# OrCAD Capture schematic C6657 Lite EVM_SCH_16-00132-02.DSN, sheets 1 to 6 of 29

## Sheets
1 PAGE06 : POWER SEQUENCE: title: POWER SEQUENCE; rev: 2.9; company: eInfochips; note: TMDSEVM6657
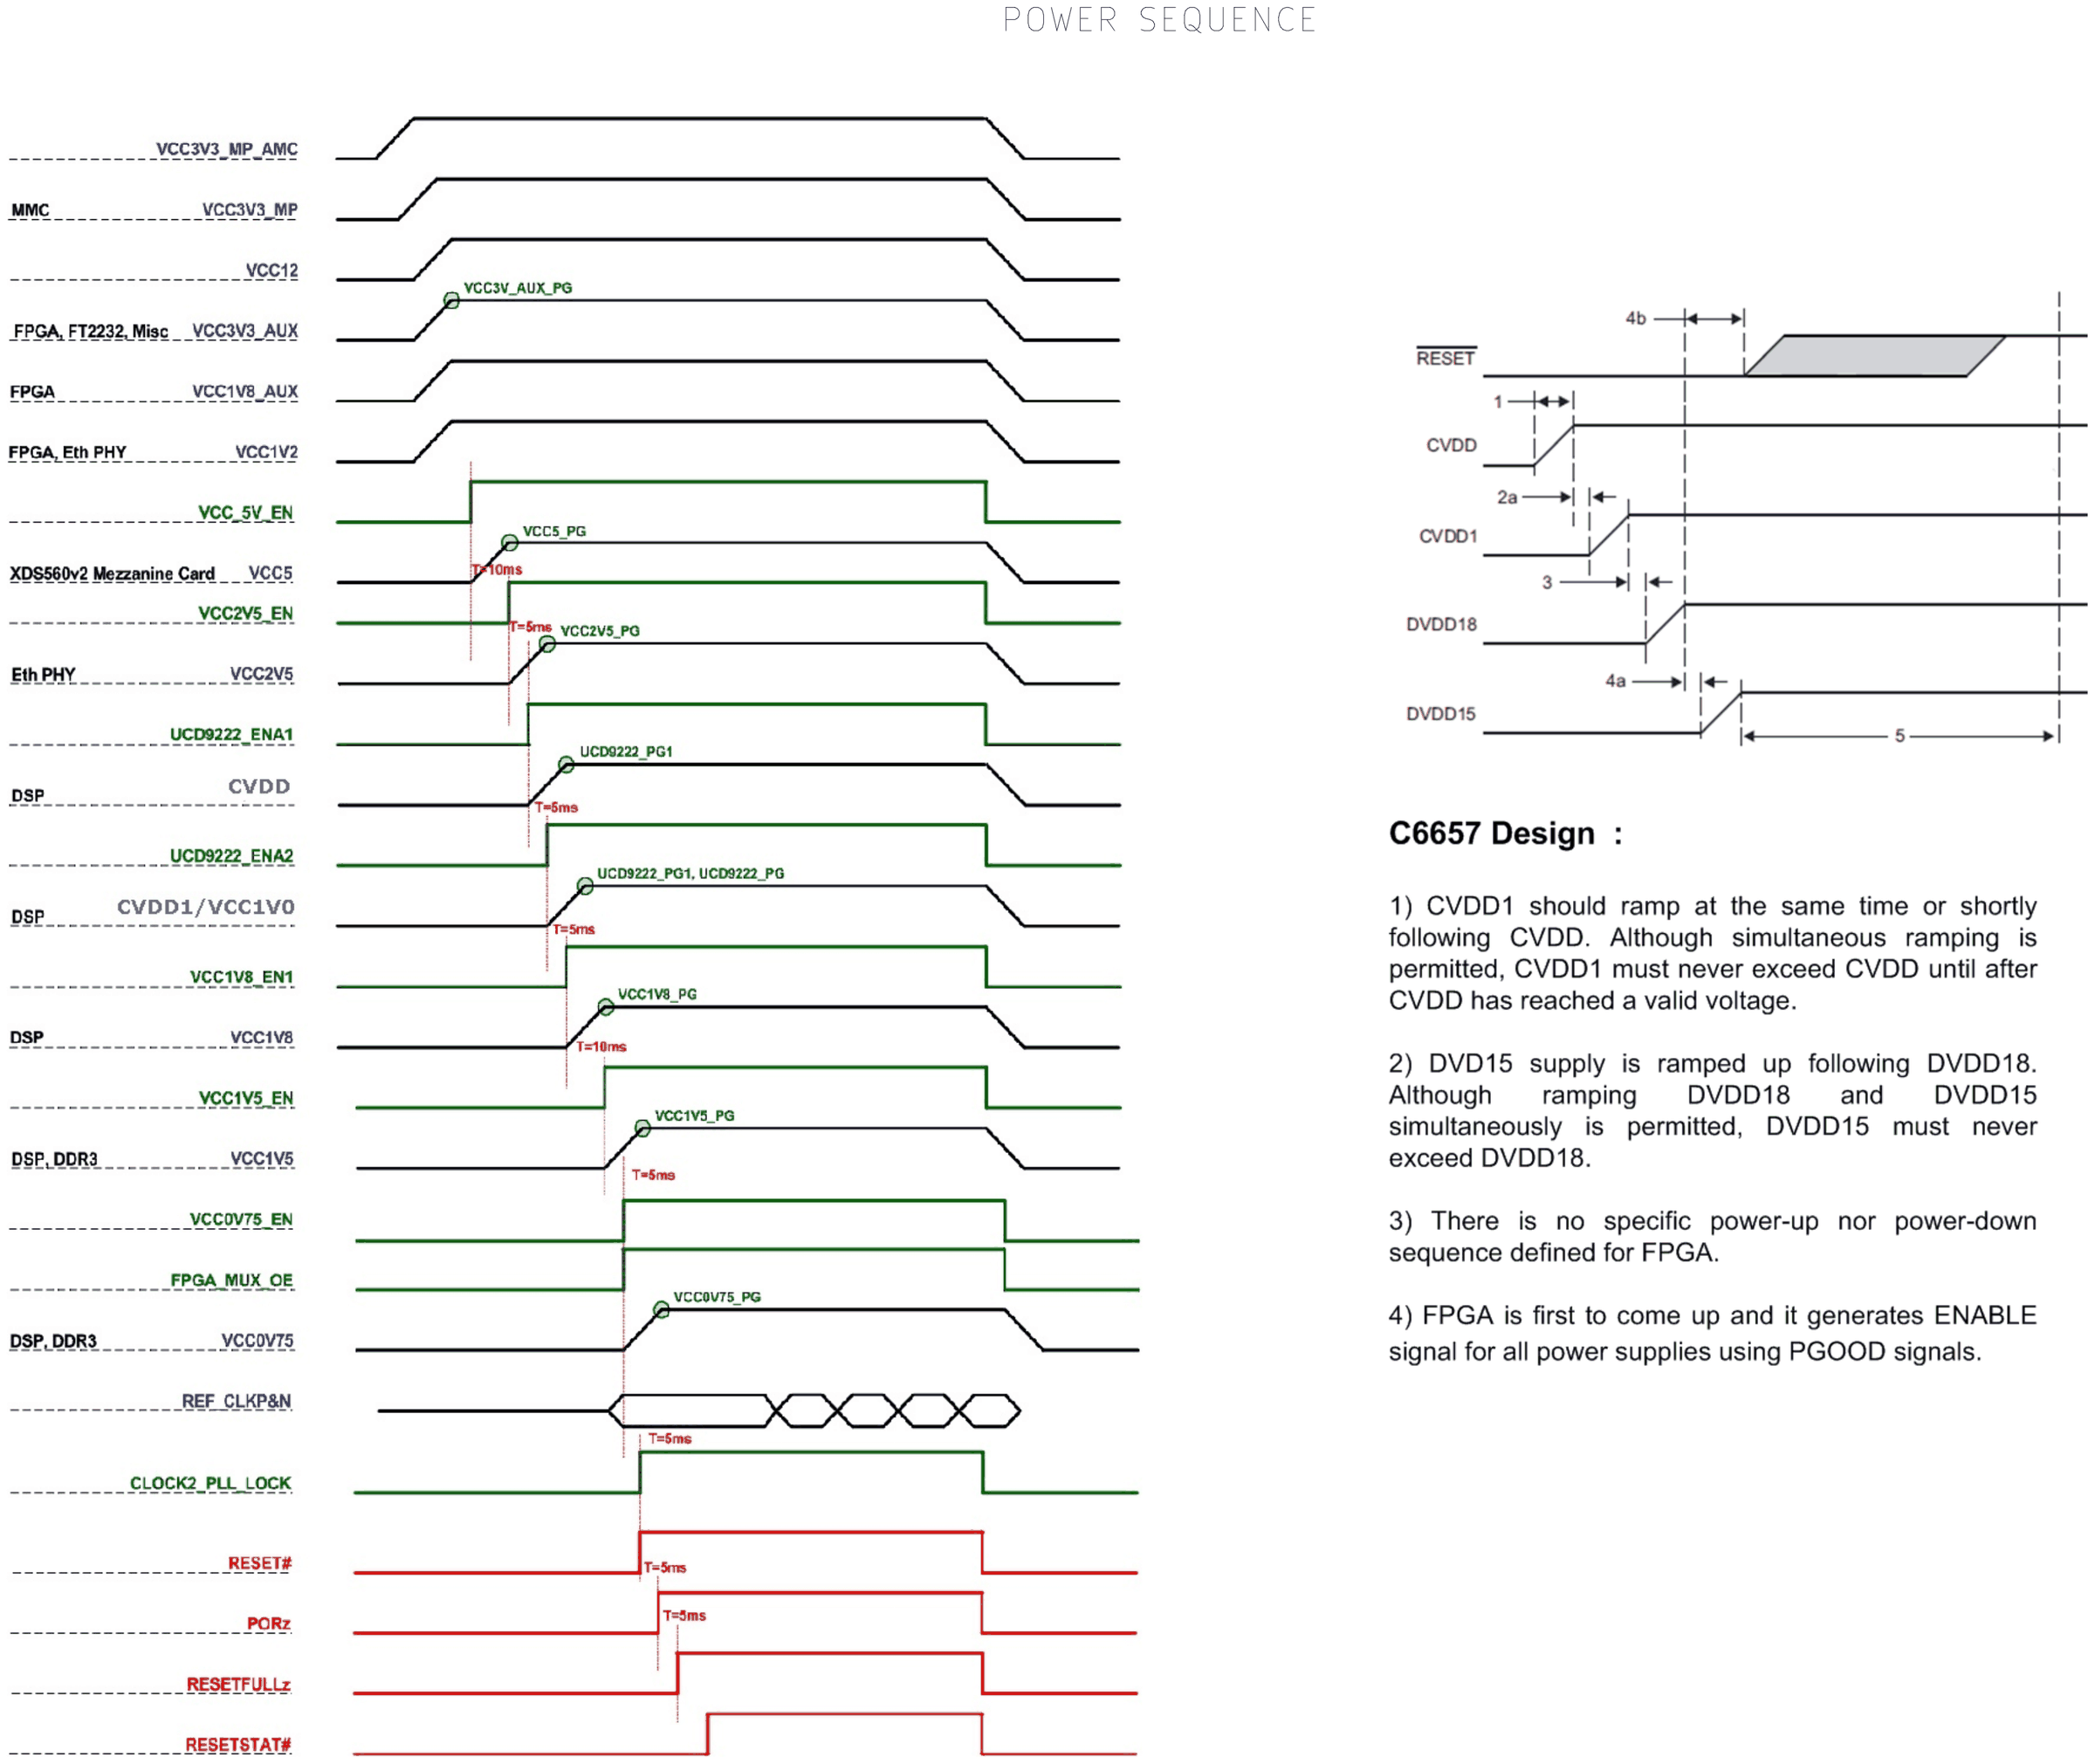
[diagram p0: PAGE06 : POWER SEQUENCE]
2 PAGE01 : COVER PAGE: title: COVER PAGE
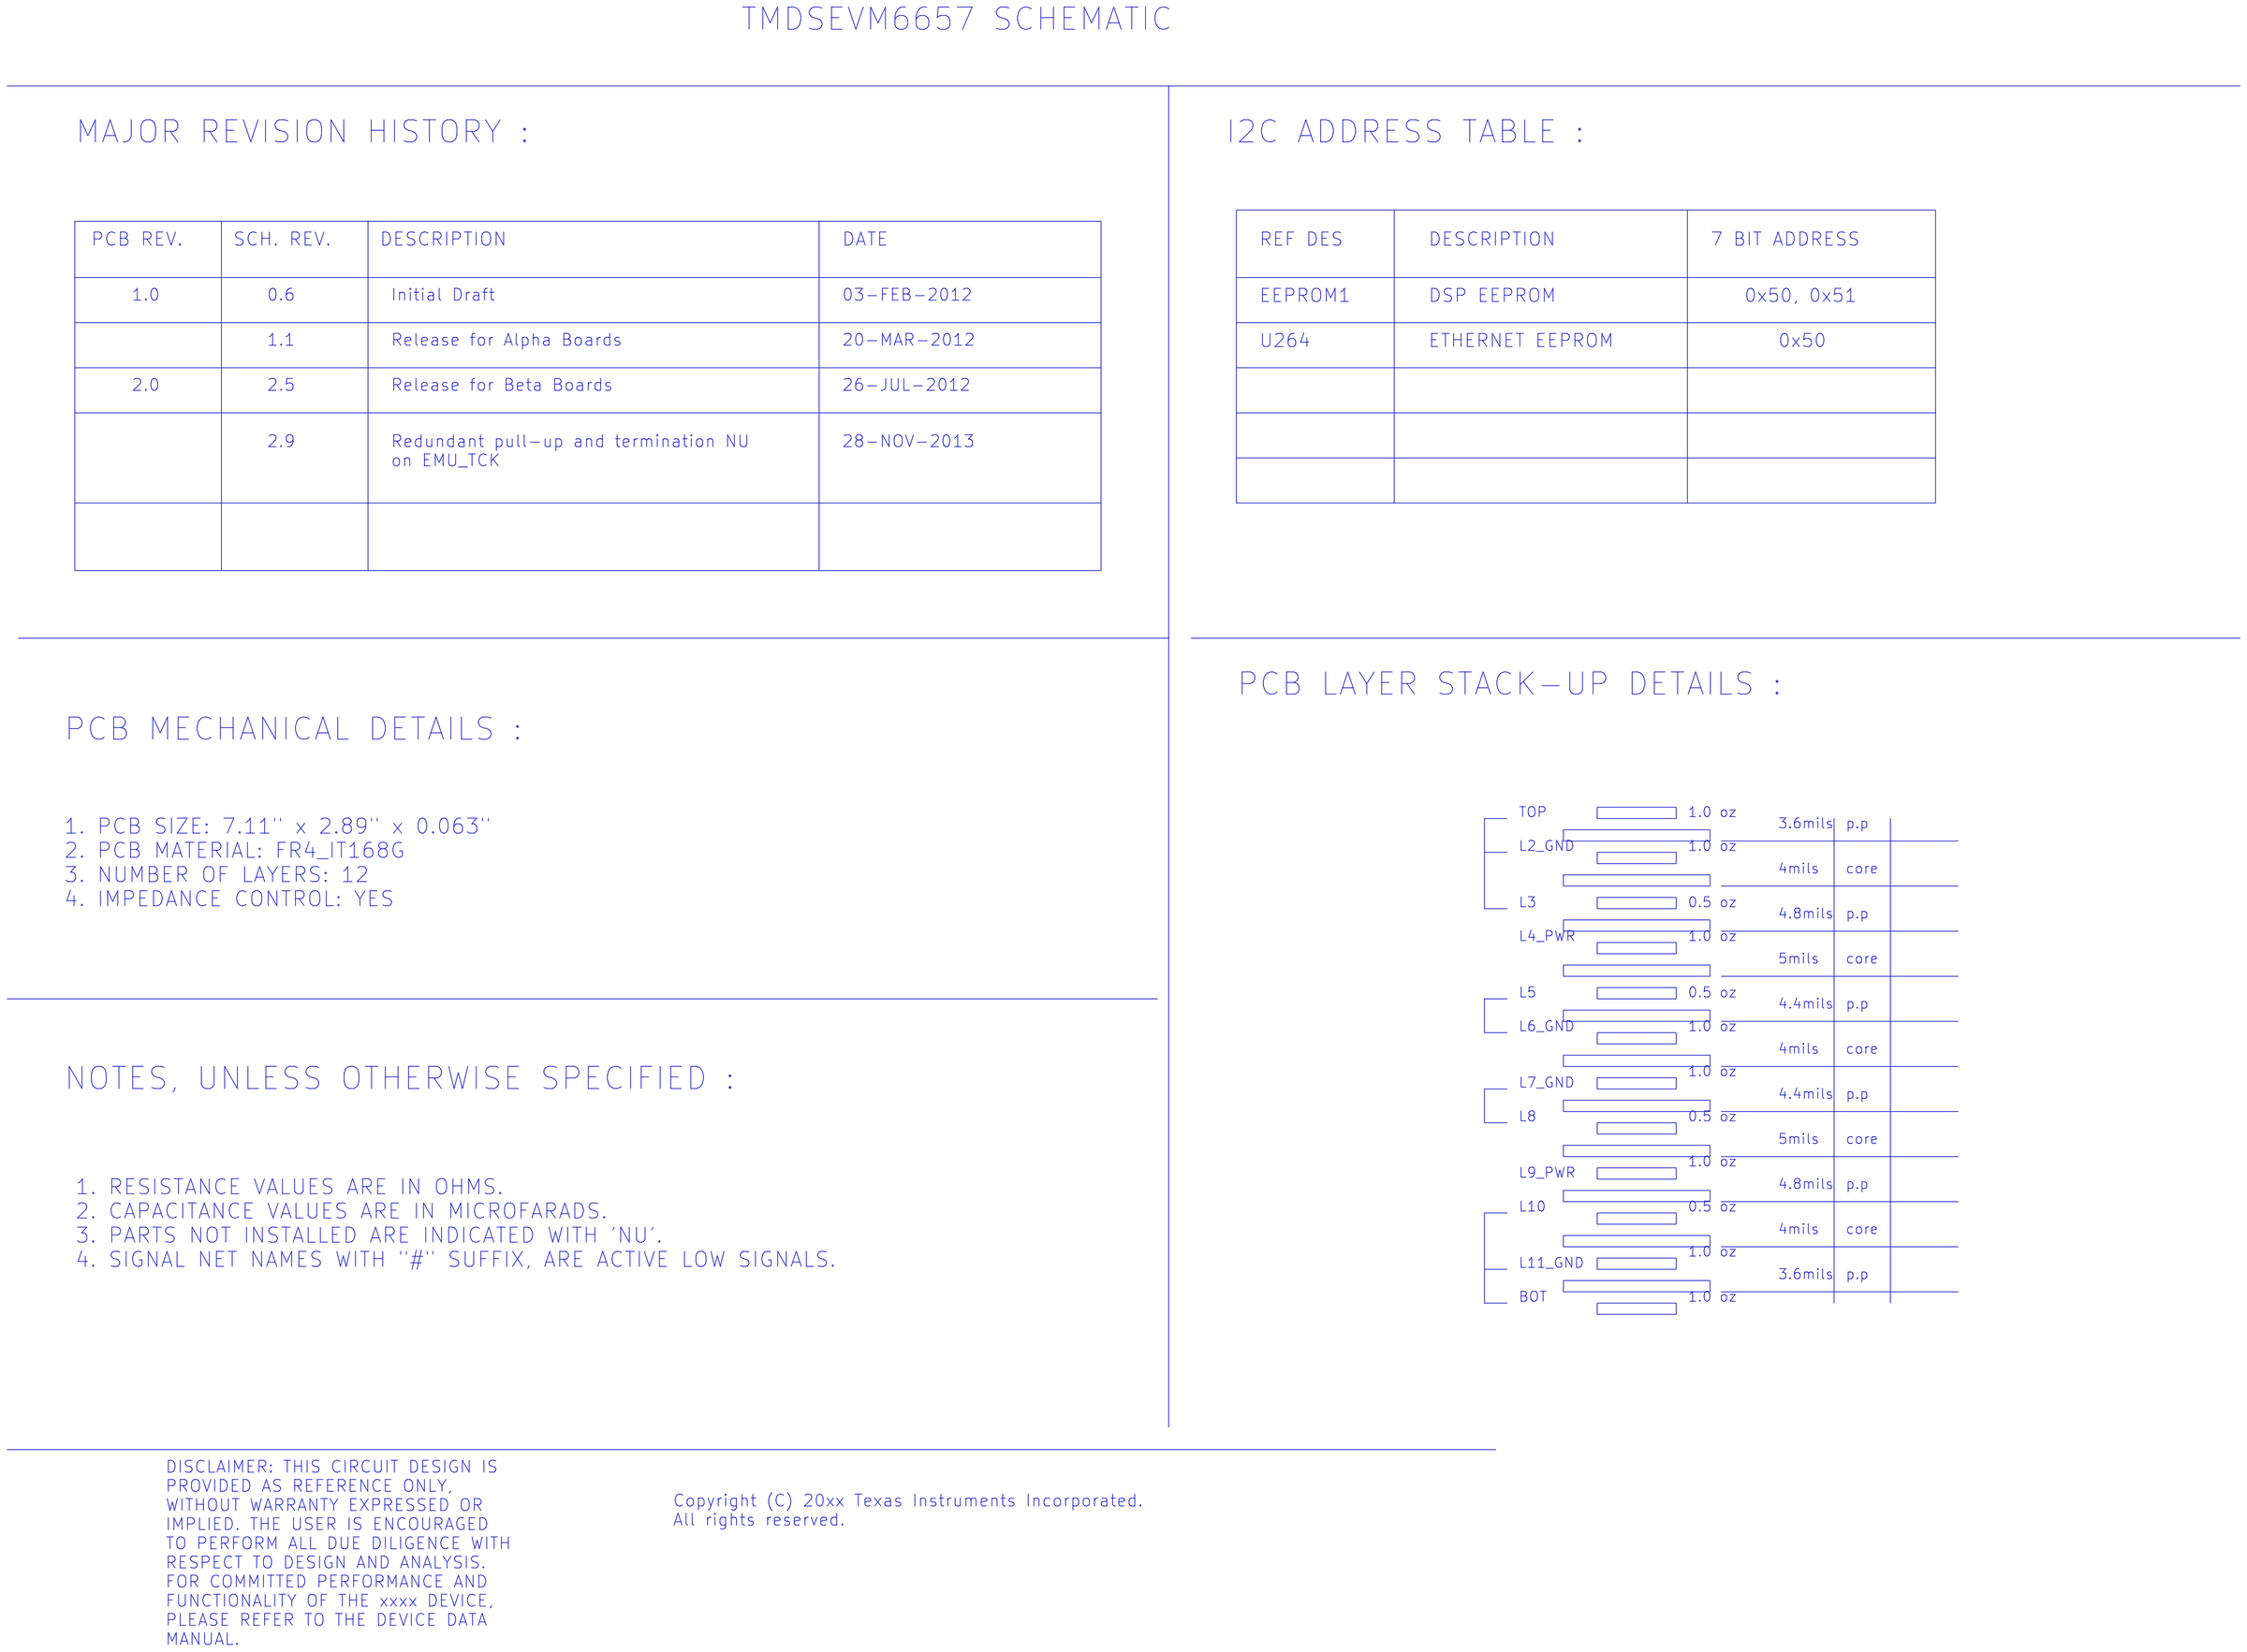
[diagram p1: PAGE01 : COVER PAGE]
3 PAGE04 : PLACEMENT: title: PLACEMENT
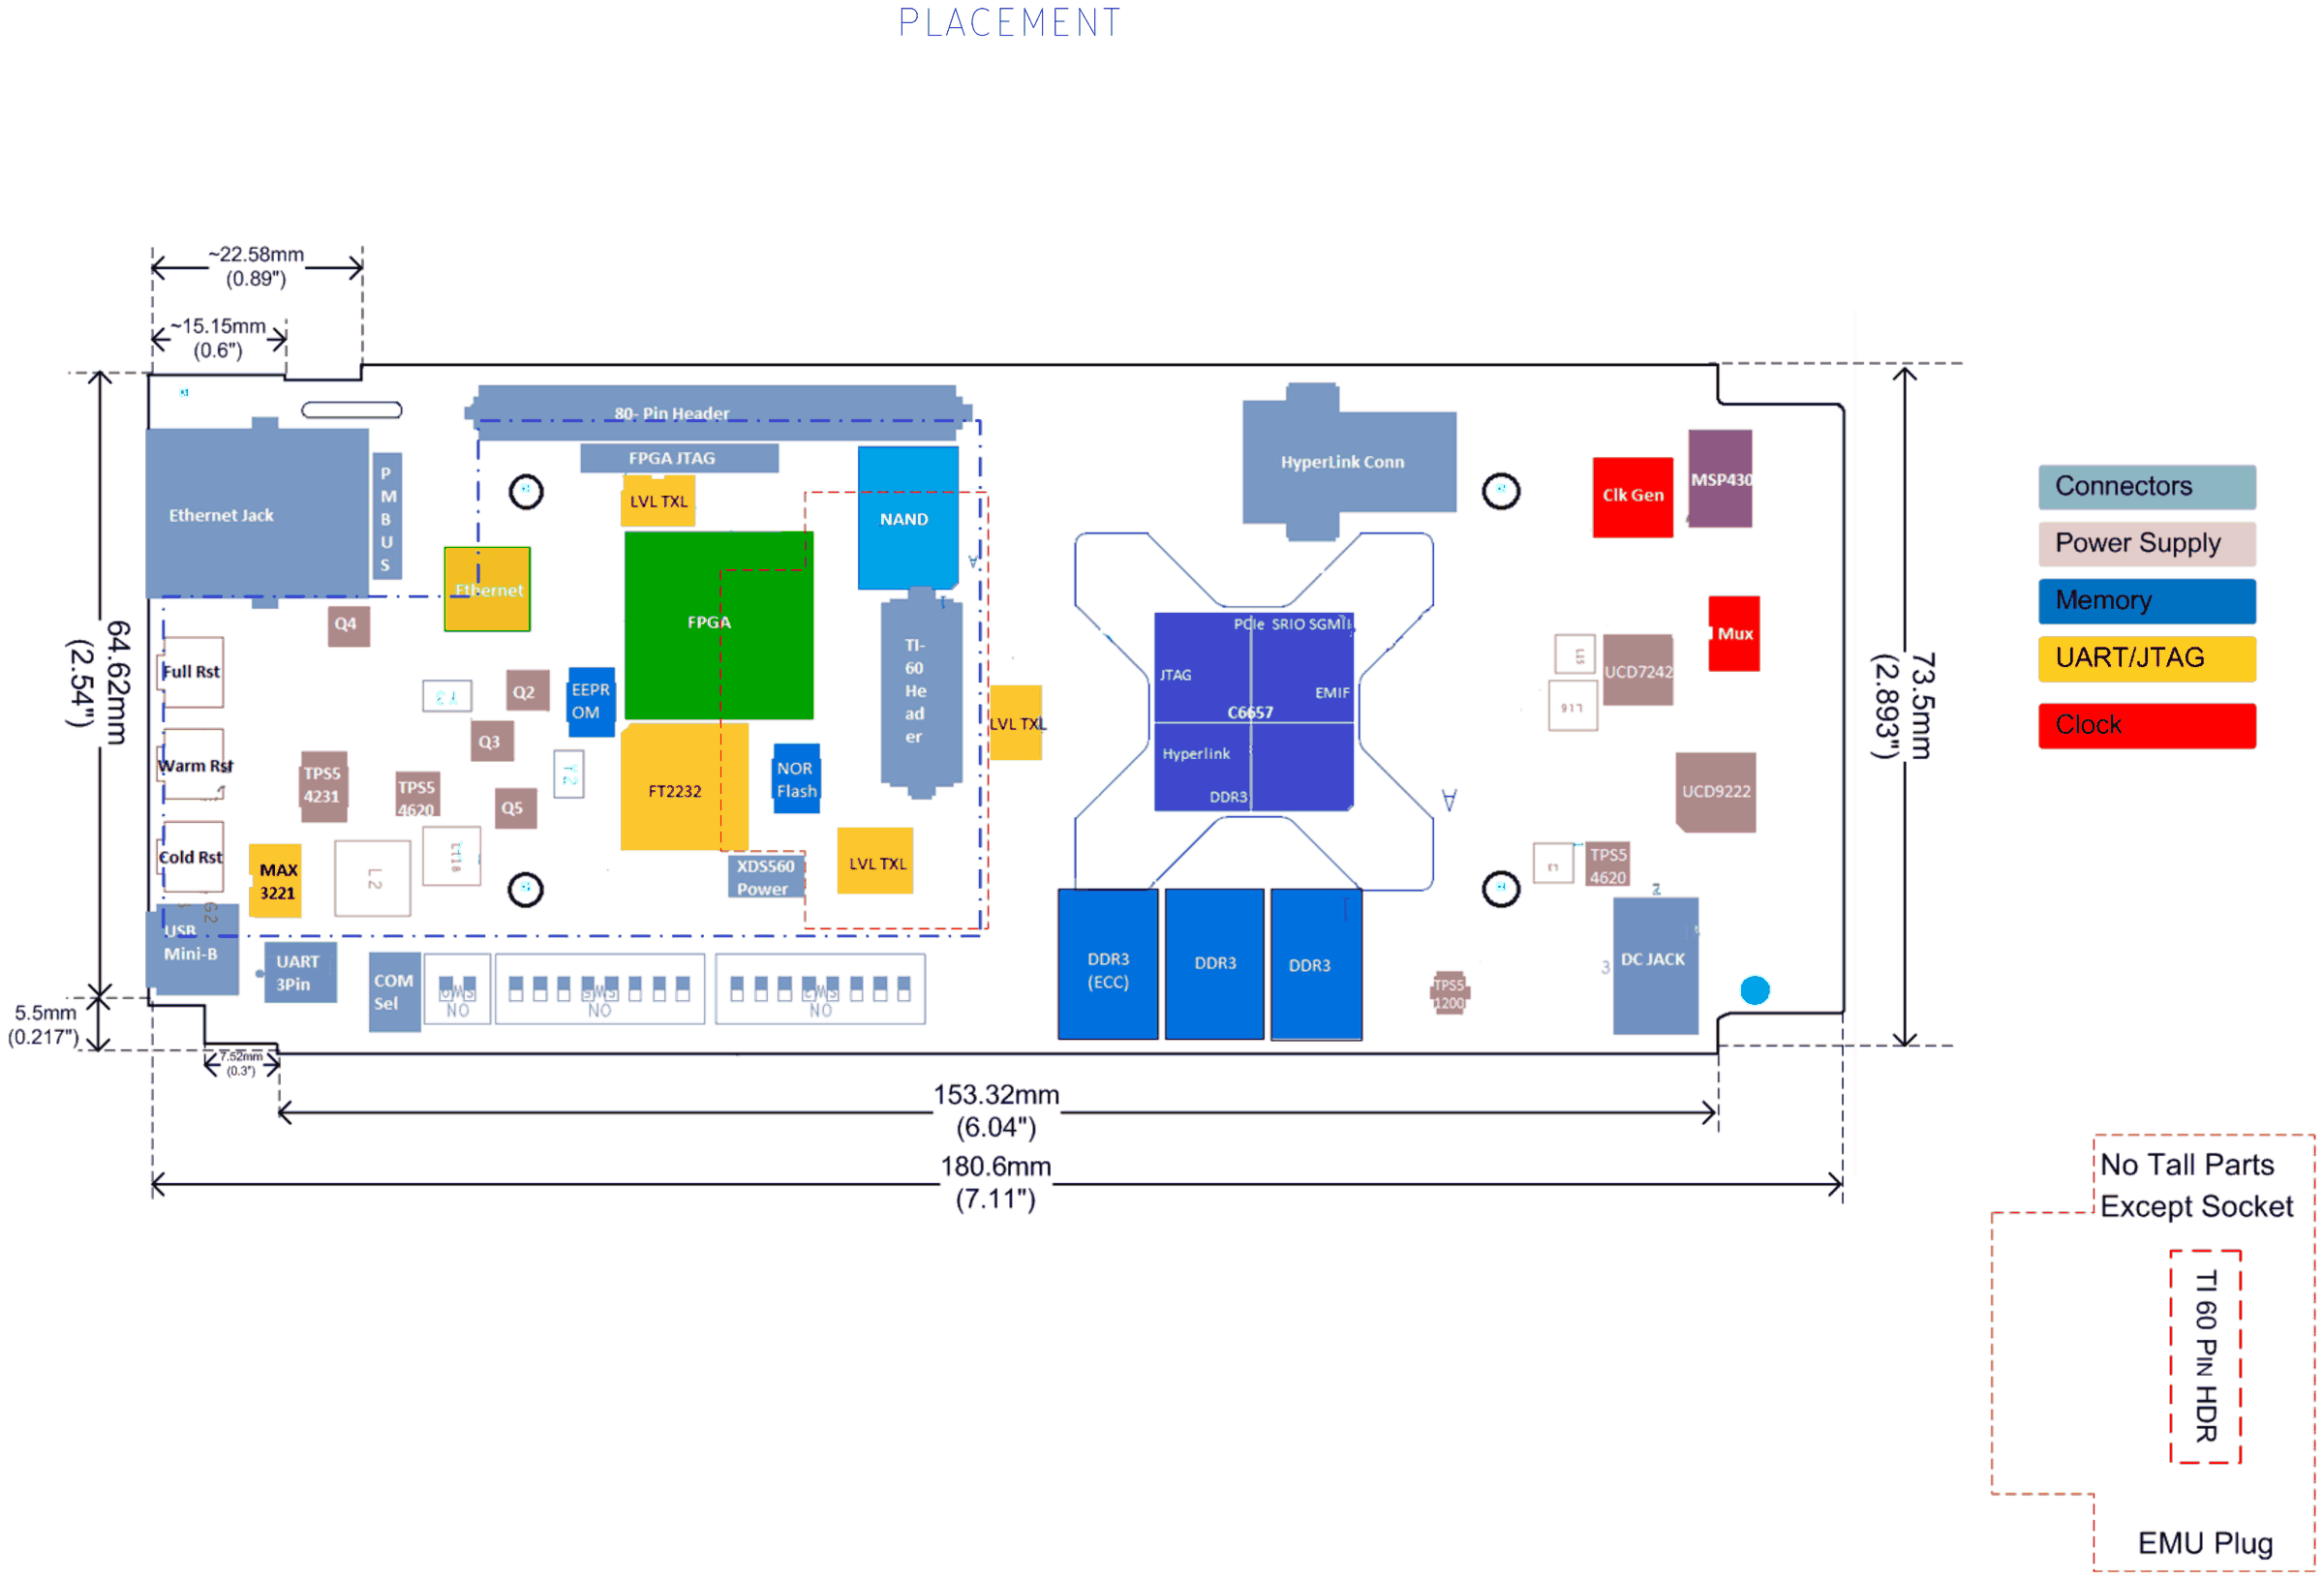
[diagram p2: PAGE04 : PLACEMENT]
4 PAGE17 : DSP_MISC: size C; title: DSP MISC
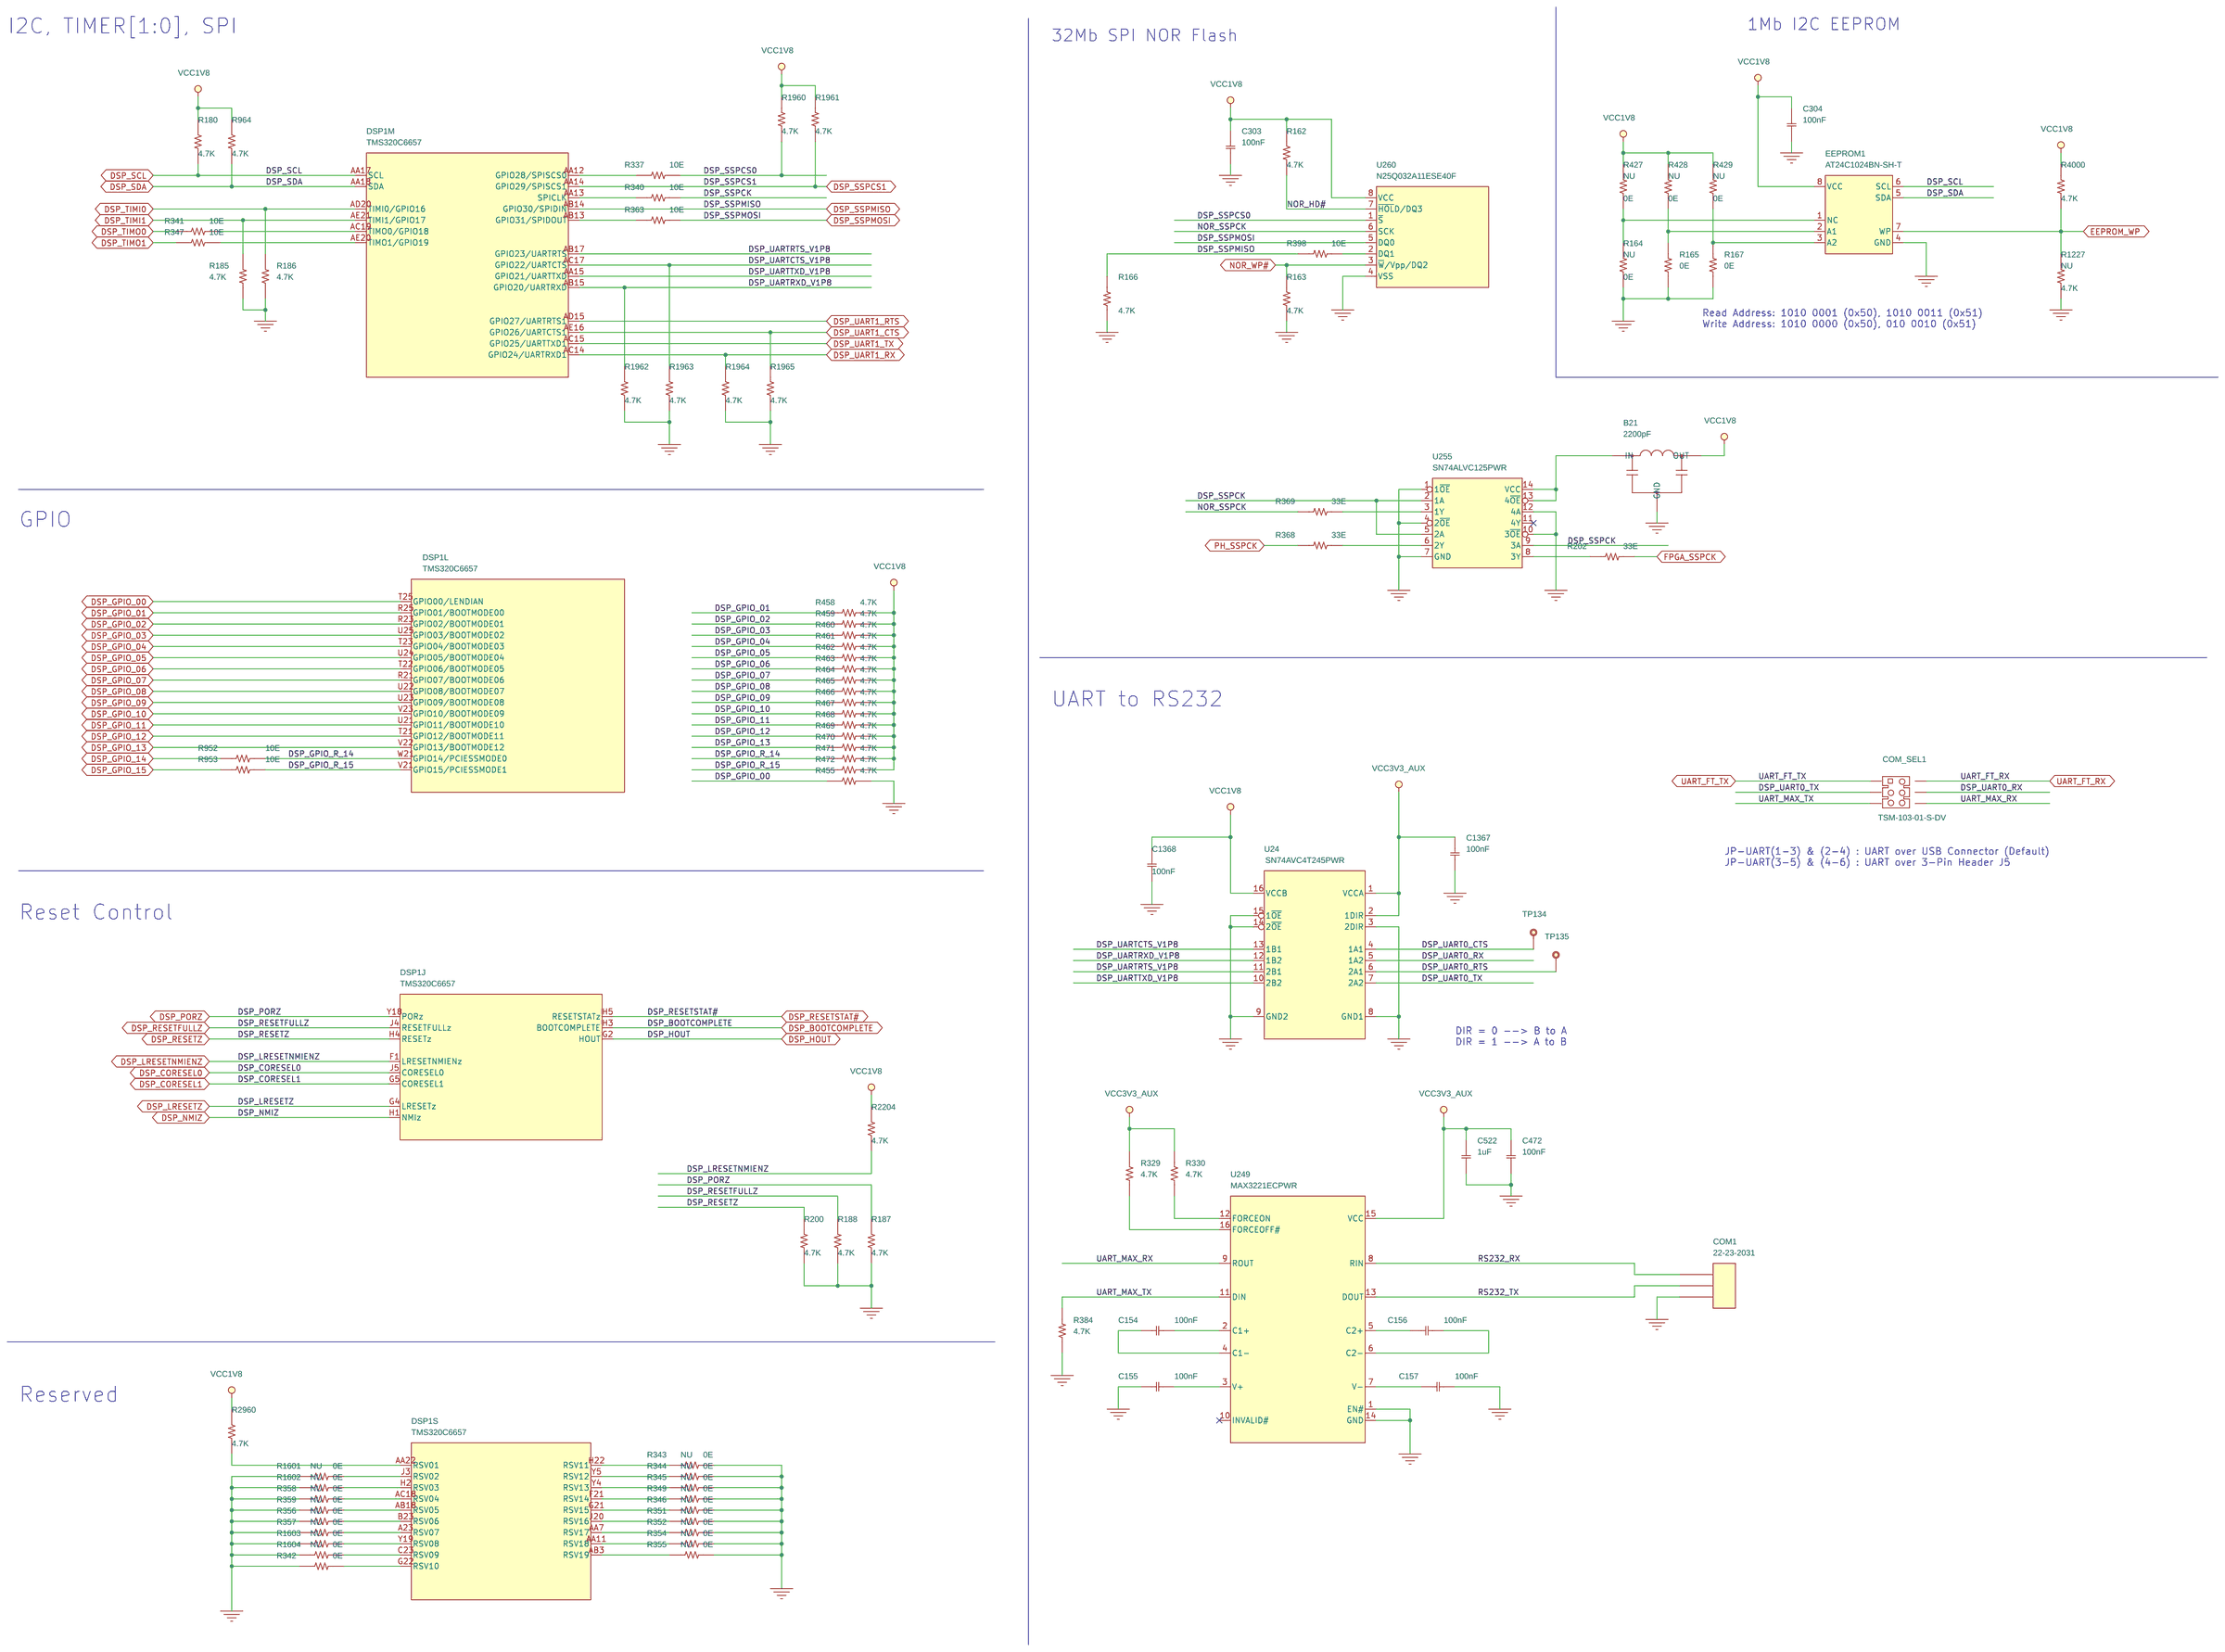
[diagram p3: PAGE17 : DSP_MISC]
5 PAGE14 : DSP_DDR3: size C; title: DSP DDR3
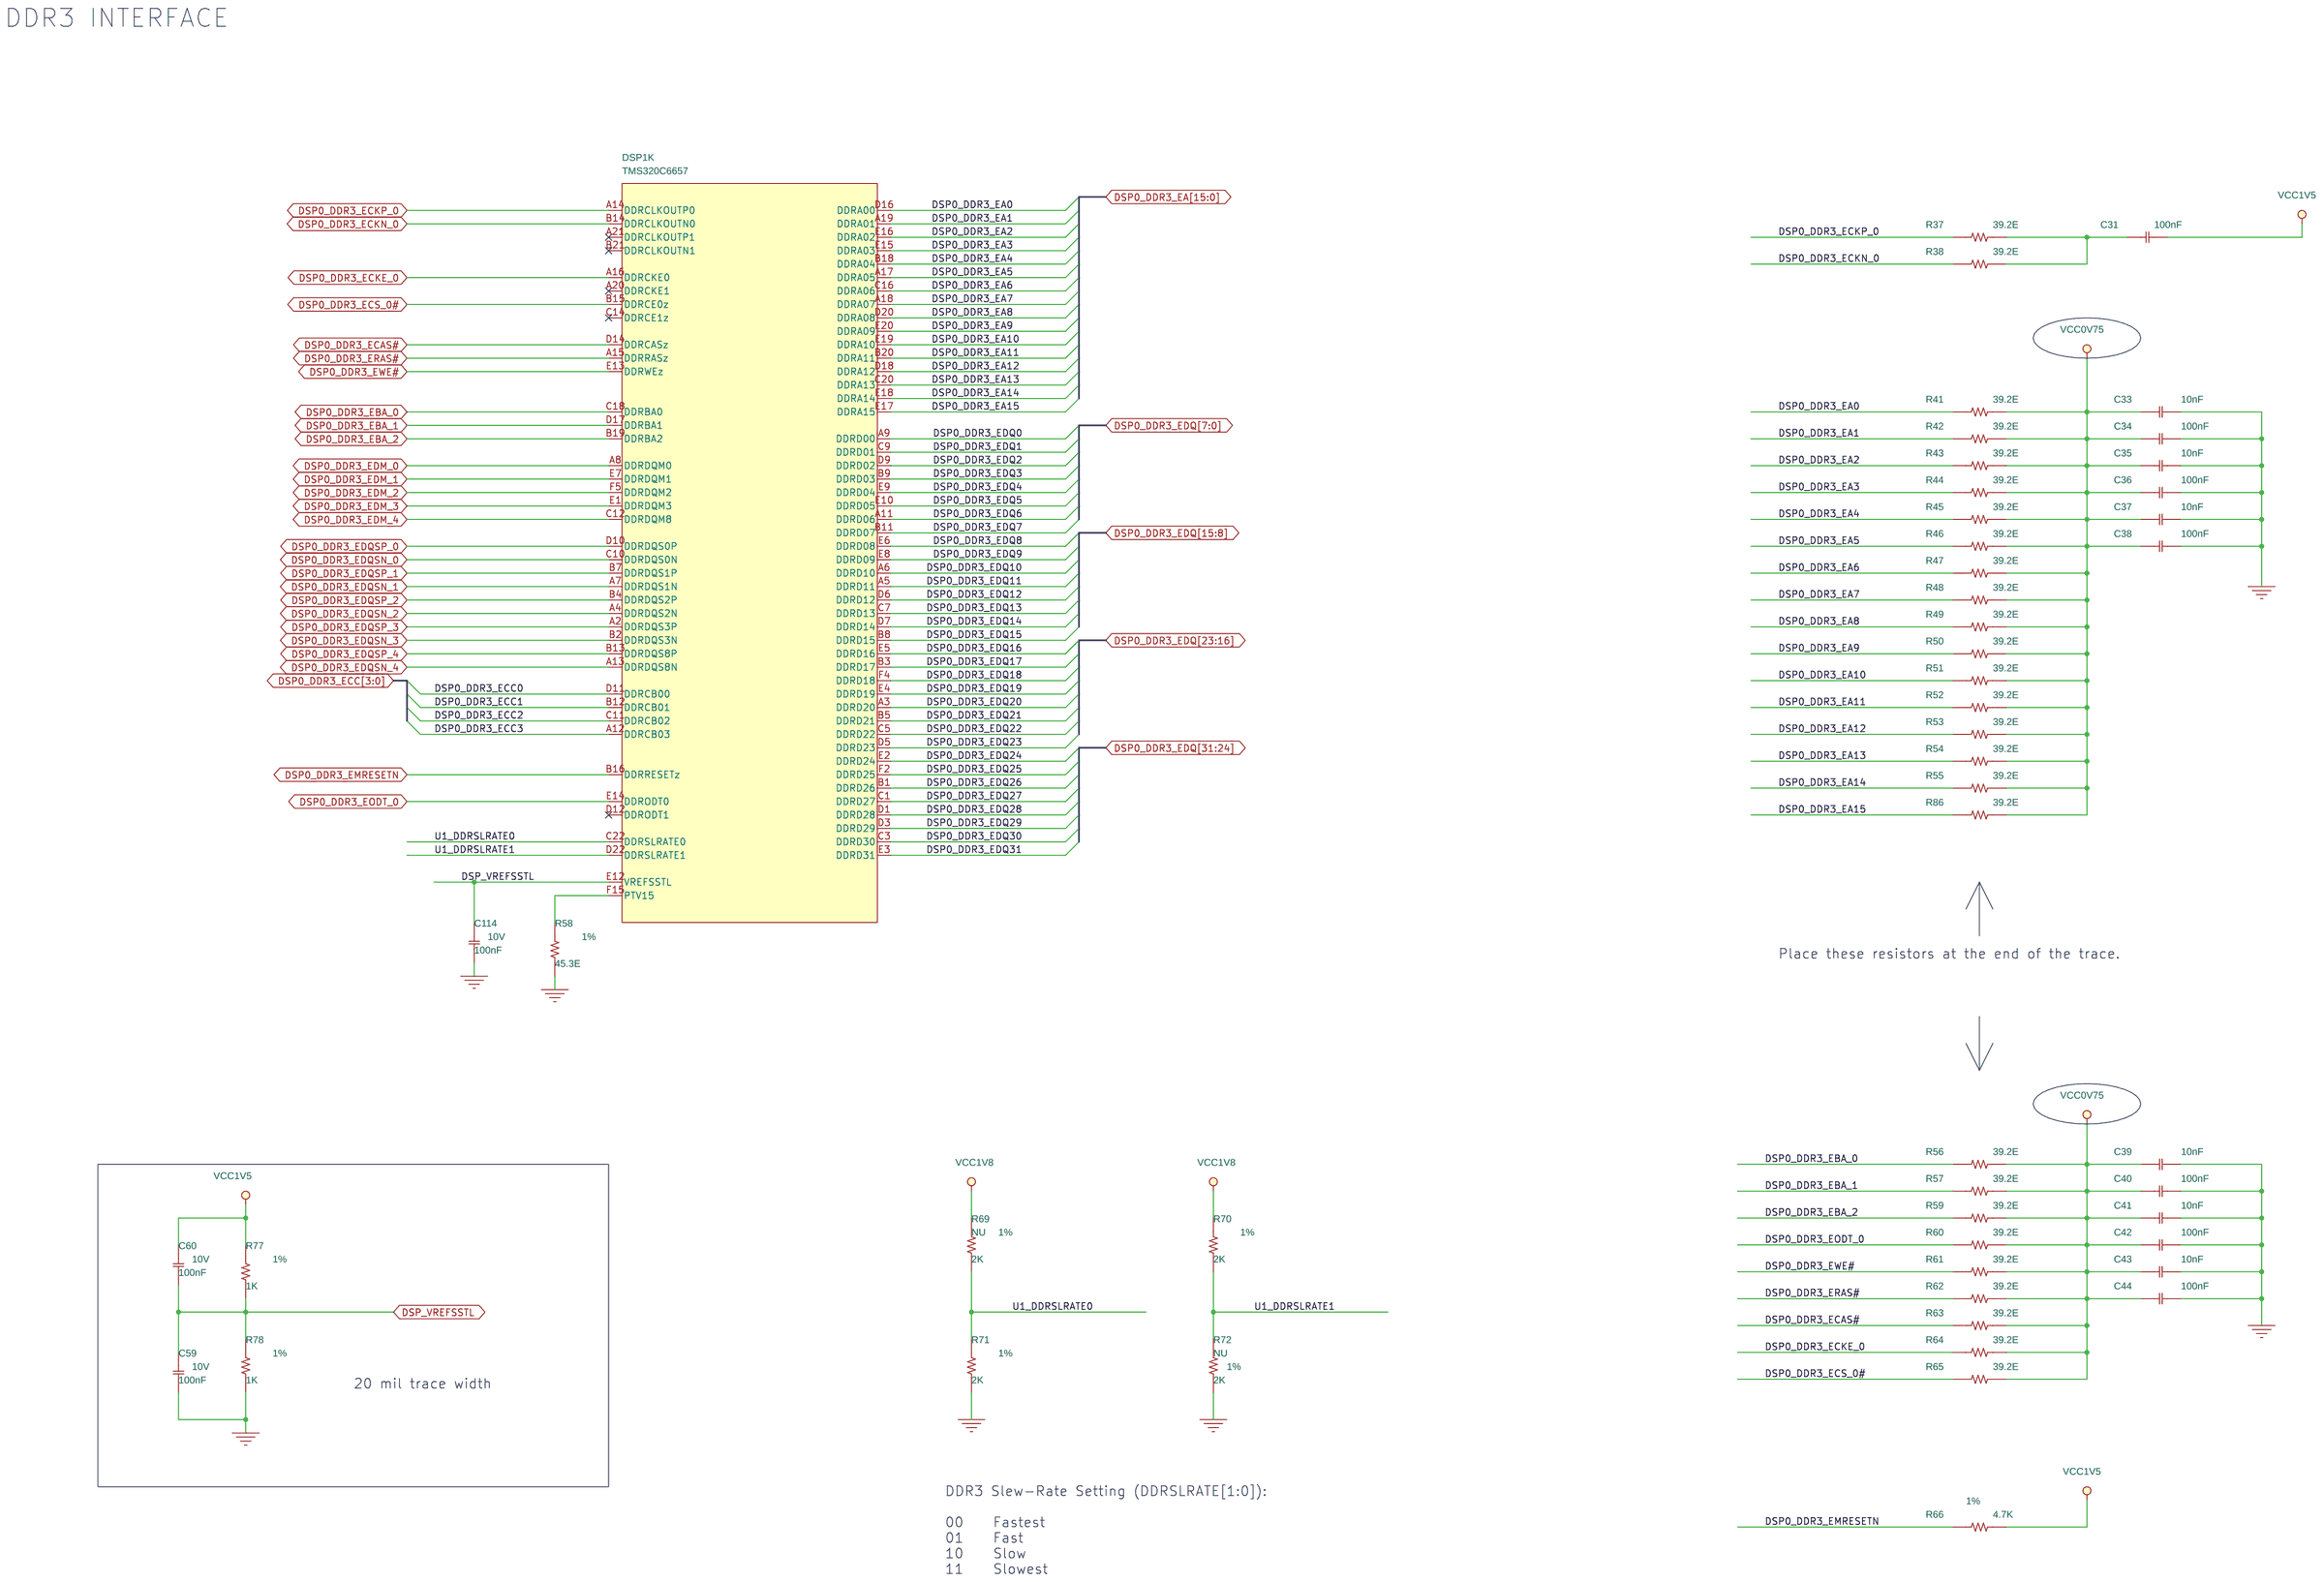
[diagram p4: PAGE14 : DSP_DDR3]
6 PAGE20 : USB-JTAG: size C; title: USB-JTAG
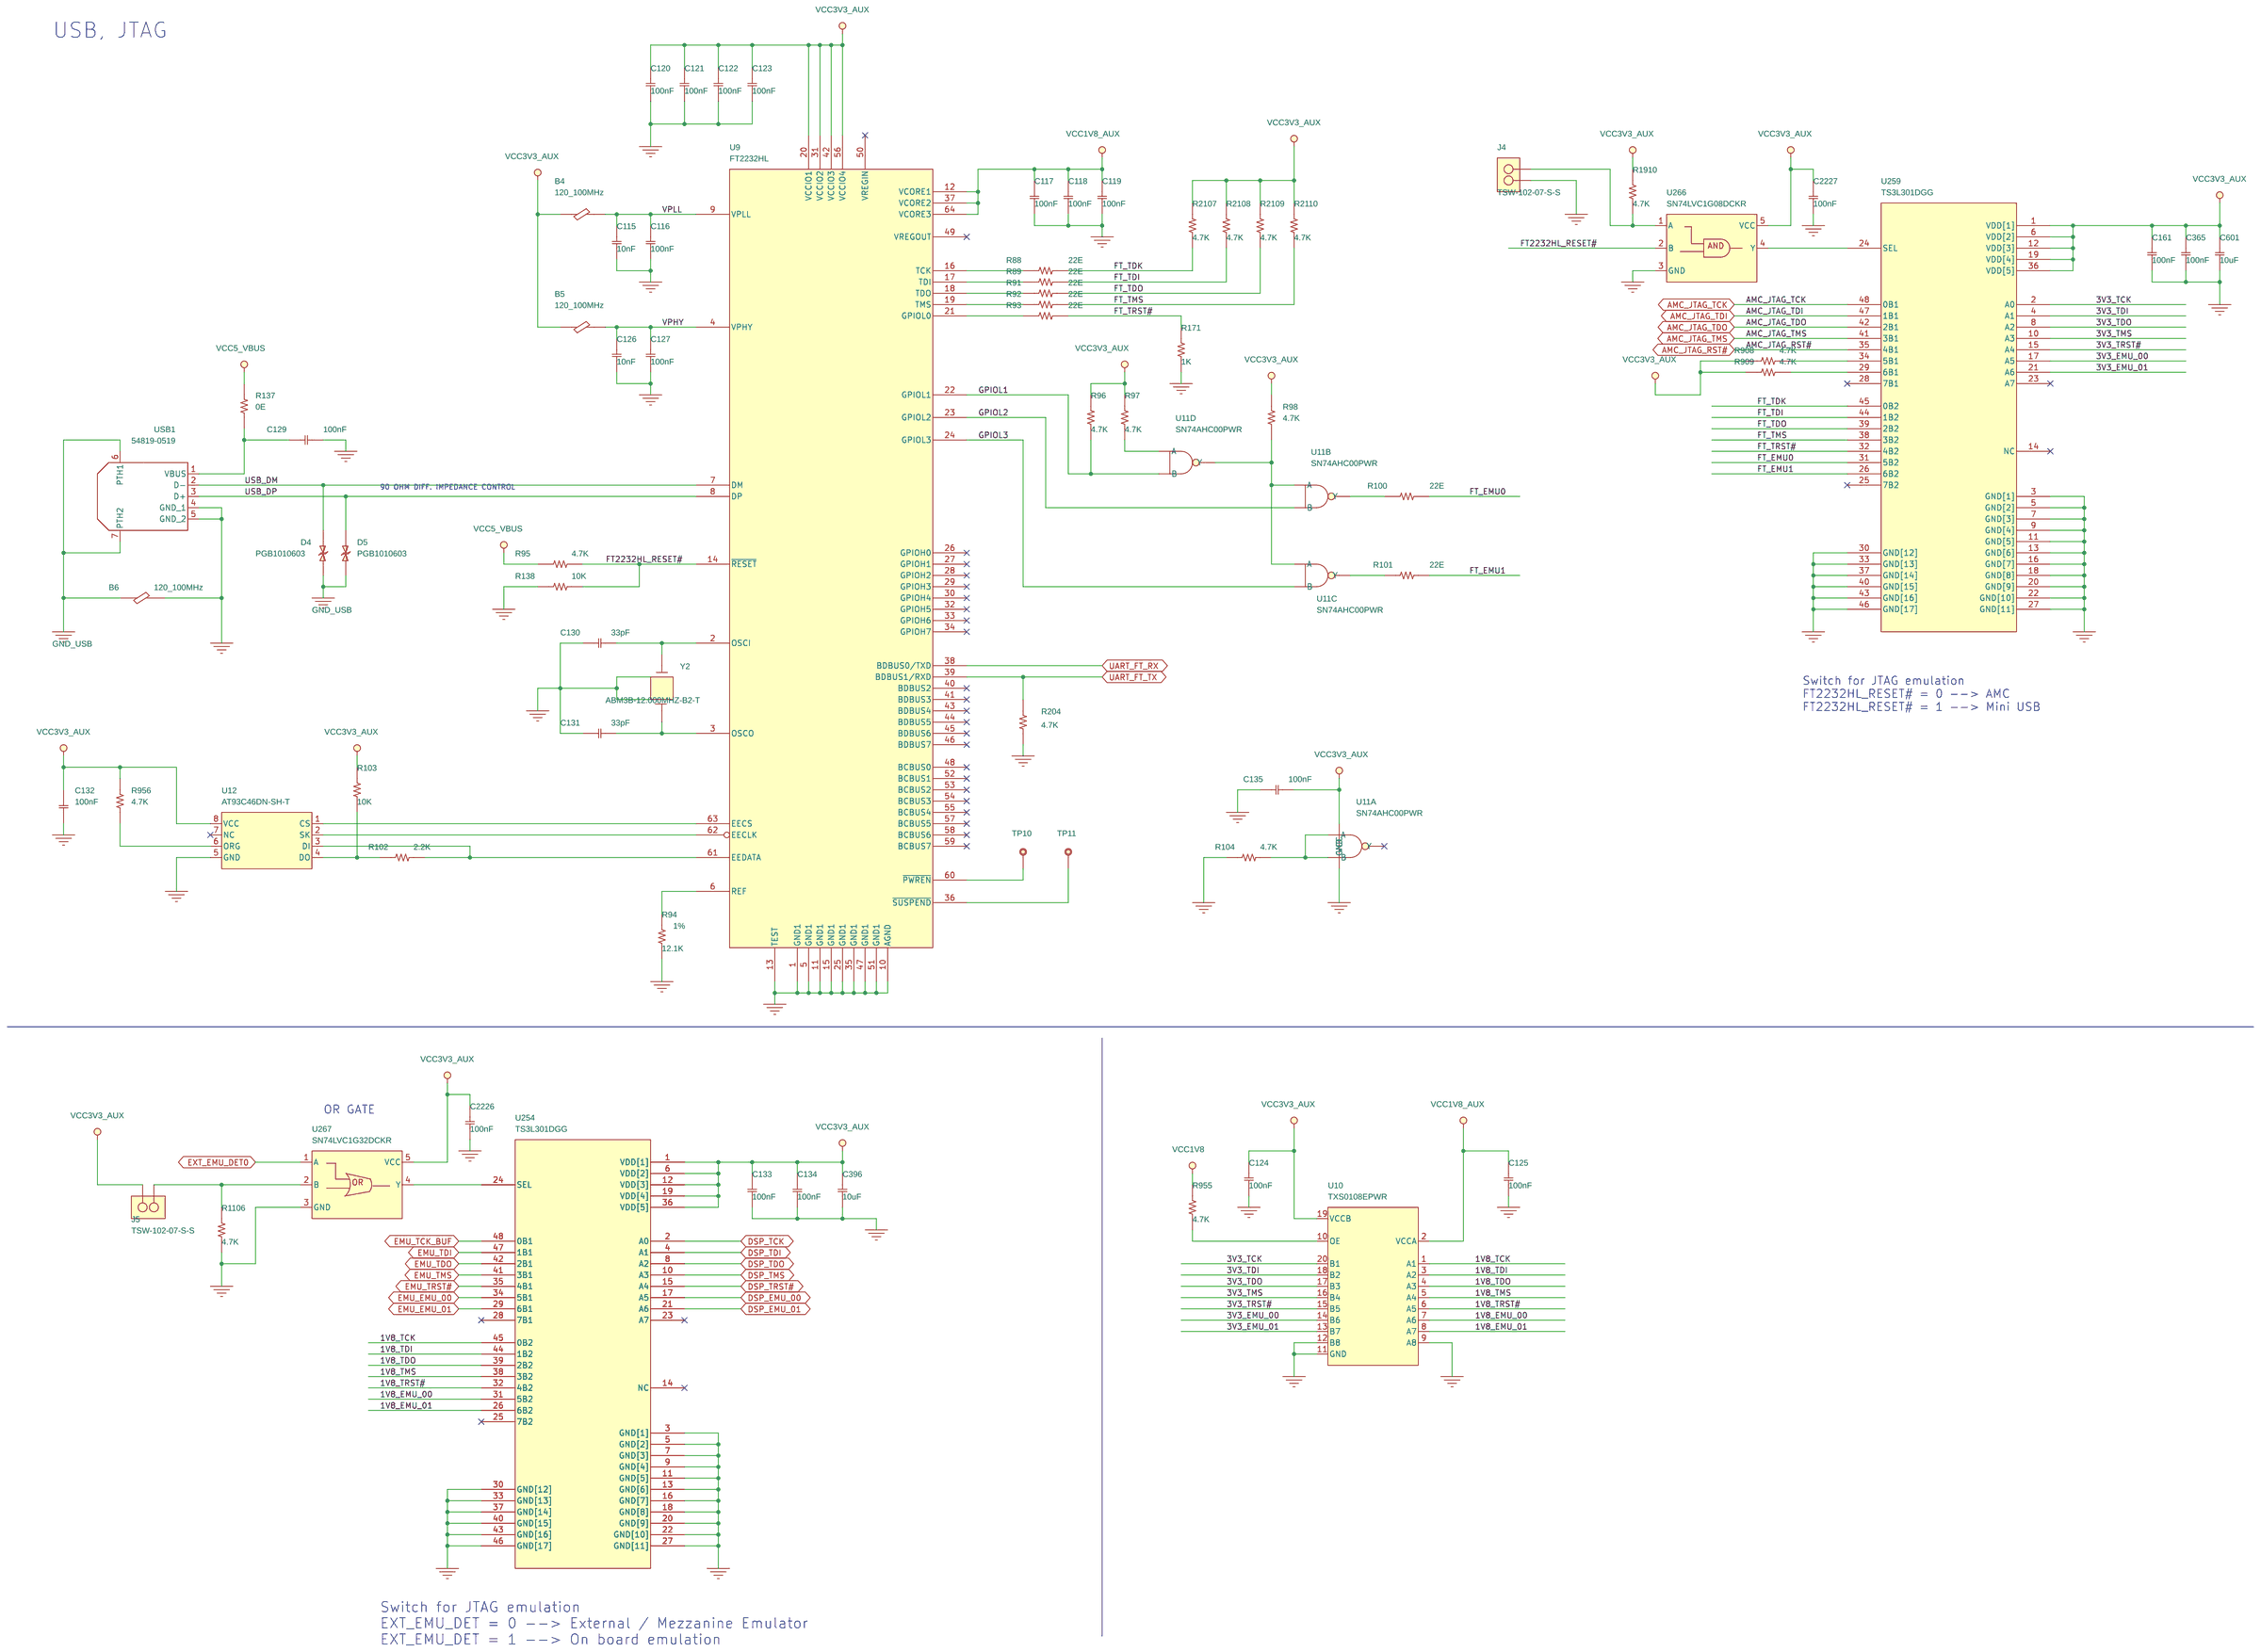
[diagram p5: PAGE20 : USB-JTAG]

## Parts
sheet PAGE14 : DSP_DDR3
C31  100nF  [C0402]
C33  10nF  [C0402]
C34  100nF  [C0402]
C35  10nF  [C0402]
C36  100nF  [C0402]
C37  10nF  [C0402]
C38  100nF  [C0402]
C39  10nF  [C0402]
C40  100nF  [C0402]
C41  10nF  [C0402]
C42  100nF  [C0402]
C43  10nF  [C0402]
C44  100nF  [C0402]
C59  100nF  [C0402]
C60  100nF  [C0402]
C114  100nF  [C0402]
R37  39.2E  [R0402]
R38  39.2E  [R0402]
R41  39.2E  [R0402]
R42  39.2E  [R0402]
R43  39.2E  [R0402]
R44  39.2E  [R0402]
R45  39.2E  [R0402]
R46  39.2E  [R0402]
R47  39.2E  [R0402]
R48  39.2E  [R0402]
R49  39.2E  [R0402]
R50  39.2E  [R0402]
R51  39.2E  [R0402]
R52  39.2E  [R0402]
R53  39.2E  [R0402]
R54  39.2E  [R0402]
R55  39.2E  [R0402]
R56  39.2E  [R0402]
R57  39.2E  [R0402]
R58  45.3E  [R0402]
R59  39.2E  [R0402]
R60  39.2E  [R0402]
R61  39.2E  [R0402]
R62  39.2E  [R0402]
R63  39.2E  [R0402]
R64  39.2E  [R0402]
R65  39.2E  [R0402]
R66  4.7K  [R0402]
R69  2K  [R0402]
R70  2K  [R0402]
R71  2K  [R0402]
R72  2K  [R0402]
R77  1K  [R0402]
R78  1K  [R0402]
R86  39.2E  [R0402]
sheet PAGE17 : DSP_MISC
B21  2200pF  [L_3P_70_63X35]
C154  100nF  [C0402]
C155  100nF  [C0402]
C156  100nF  [C0402]
C157  100nF  [C0402]
C303  100nF  [C0402]
C304  100nF  [C0402]
C472  100nF  [C0402]
C522  1uF  [C0402]
C1367  100nF  [C0402]
C1368  100nF  [C0402]
COM1  22-23-2031  [MOL22-23-2031]
COM_SEL1  TSM-103-01-S-DV  [SAMTSM-103-01-S-DV]
EEPROM1  AT24C1024BN-SH-T  [SOIC_8P_50_193X236]
R162  4.7K  [R0402]
R163  4.7K  [R0402]
R164  0E  [R0402]
R165  0E  [R0402]
R166  4.7K  [R0402]
R167  0E  [R0402]
R180  4.7K  [R0402]
R185  4.7K  [R0402]
R186  4.7K  [R0402]
R187  4.7K  [R0402]
R188  4.7K  [R0402]
R200  4.7K  [R0402]
R202  33E  [R0402]
R329  4.7K  [R0402]
R330  4.7K  [R0402]
R337  10E  [R0402]
R340  10E  [R0402]
R341  10E  [R0402]
R342  0E  [R0402]
R343  0E  [R0402]
R344  0E  [R0402]
R345  0E  [R0402]
R346  0E  [R0402]
R347  10E  [R0402]
R349  0E  [R0402]
R351  0E  [R0402]
R352  0E  [R0402]
R354  0E  [R0402]
R355  0E  [R0402]
R356  0E  [R0402]
R357  0E  [R0402]
R358  0E  [R0402]
R359  0E  [R0402]
R363  10E  [R0402]
R368  33E  [R0402]
R369  33E  [R0402]
R384  4.7K  [R0402]
R398  10E  [R0402]
R427  0E  [R0402]
R428  0E  [R0402]
R429  0E  [R0402]
R455  4.7K  [R0402]
R458  4.7K  [R0402]
R459  4.7K  [R0402]
R460  4.7K  [R0402]
R461  4.7K  [R0402]
R462  4.7K  [R0402]
R463  4.7K  [R0402]
R464  4.7K  [R0402]
R465  4.7K  [R0402]
R466  4.7K  [R0402]
R467  4.7K  [R0402]
R468  4.7K  [R0402]
R469  4.7K  [R0402]
R470  4.7K  [R0402]
R471  4.7K  [R0402]
R472  4.7K  [R0402]
R952  10E  [R0402]
R953  10E  [R0402]
R964  4.7K  [R0402]
R1227  4.7K  [R0402]
R1601  0E  [R0402]
R1602  0E  [R0402]
R1603  0E  [R0402]
R1604  0E  [R0402]
R1960  4.7K  [R0402]
R1961  4.7K  [R0402]
R1962  4.7K  [R0402]
R1963  4.7K  [R0402]
R1964  4.7K  [R0402]
R1965  4.7K  [R0402]
R2204  4.7K  [R0402]
R2960  4.7K  [R0402]
R4000  4.7K  [R0402]
TP134  Test Point  [TP-S40]
TP135  Test Point  [TP-S40]
U24  SN74AVC4T245PWR  [SOIC_16P_26_197x252]
U249  MAX3221ECPWR  [SOIC_16P_26_197x252]
U255  SN74ALVC125PWR  [SOIC_14P_26_197X252]
U260  N25Q032A11ESE40F  [SOP127P790_8]
sheet PAGE20 : USB-JTAG
B4  120_100MHz  [L0402]
B5  120_100MHz  [L0402]
B6  120_100MHz  [L0402]
C115  10nF  [C0402]
C116  100nF  [C0402]
C117  100nF  [C0402]
C118  100nF  [C0402]
C119  100nF  [C0402]
C120  100nF  [C0402]
C121  100nF  [C0402]
C122  100nF  [C0402]
C123  100nF  [C0402]
C124  100nF  [C0402]
C125  100nF  [C0402]
C126  10nF  [C0402]
C127  100nF  [C0402]
C129  100nF  [C0402]
C130  33pF  [C0402]
C131  33pF  [C0402]
C132  100nF  [C0402]
C133  100nF  [C0402]
C134  100nF  [C0402]
C135  100nF  [C0402]
C161  100nF  [C0402]
C365  100nF  [C0402]
C396  10uF  [C0603]
C601  10uF  [C0603]
C2226  100nF  [C0402]
C2227  100nF  [C0402]
D4  PGB1010603  [ESD_2P_65_63X31]
D5  PGB1010603  [ESD_2P_65_63X31]
J4  TSW-102-07-S-S  [SAMTSW-102-07-S-S]
J5  TSW-102-07-S-S  [SAMTSW-102-07-S-S]
R88  22E  [R0402]
R89  22E  [R0402]
R91  22E  [R0402]
R92  22E  [R0402]
R93  22E  [R0402]
R94  12.1K  [R0603]
R95  4.7K  [R0402]
R96  4.7K  [R0402]
R97  4.7K  [R0402]
R98  4.7K  [R0402]
R100  22E  [R0402]
R101  22E  [R0402]
R102  2.2K  [R0402]
R103  10K  [R0402]
R104  4.7K  [R0402]
R137  0E  [R0402]
R138  10K  [R0402]
R171  1K  [R0402]
R204  4.7K  [R0402]
R908  4.7K  [R0402]
R909  4.7K  [R0402]
R955  4.7K  [R0402]
R956  4.7K  [R0402]
R1106  4.7K  [R0402]
R1910  4.7K  [R0402]
R2107  4.7K  [R0402]
R2108  4.7K  [R0402]
R2109  4.7K  [R0402]
R2110  4.7K  [R0402]
TP10  Test Point  [TP-S40]
TP11  Test Point  [TP-S40]
U9  FT2232HL  [QFP_64P_20_472X472]
U10  TXS0108EPWR  [SOIC_20P_26_256x252]
U11  SN74AHC00PWR  [TSSOP65P640_14]  (sections A,B,C,D)
U12  AT93C46DN-SH-T  [SOIC_8P_50_193x236]
U254  TS3L301DGG  [SOIC_48P_20_492X319]
U259  TS3L301DGG  [SOIC_48P_20_492X319]
U266  SN74LVC1G08DCKR  [SC70_5P]
U267  SN74LVC1G32DCKR  [SC70_5P]
USB1  54819-0519  [MOL54819-0519]
Y2  ABM3B-12.000MHZ-B2-T  [XTAL_ABM3B]
sheet PAGE25 : DSP_POWER 2
DSP1  TMS320C6657  [BGA80P_38X38_625_SKT_EINF]  (sections A,B,C,D,E,F,G,H,I,J,K,L,M,N,O,P,Q,R,S,T)

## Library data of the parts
C31 C34 C36 C38 C40 C42 C44 C116-C125 C127 C129 C132-C135 C154-C157 C161 C303 C304 C365 C472 C1367 C1368 C2226 C2227 = 11_C_0: CAP CER 0.1UF 10V 10% X5R 0402; Alt Mfg: Murata; Alt Mfg Part#: GRM155R61A104KA01D; Manufacture Part Number: 2238 787 15649||CC0402KRX7R7BB104; Mfg: Yageo; Mfg Part#: CC0402KRX5R6BB104; Oper. Temp. Range: -55C to 85C; Package: 0402; ProcessType: SMT; RoHS: Yes; Tolerance: 10%; Vendor: DigiKey; Vendor Part#: 311-1336-1-ND; eI Part#: 03_00021_02
C33 C35 C37 C39 C41 C43 C115 C126 = 11_C_0: CAP 10nF 16V CERAMIC 0402 SMD; Alt Mfg: Murata; Alt Mfg Part#: GRM155R71C103KA01D; Manufacture Part Number: C1005X7R1C103K||2238 787 15636||CC0402KRX7R7BB103; Mfg: Panasonic - ECG; Mfg Part#: ECJ-0EB1C103K; Oper. Temp. Range: -55C to 125C; Package: 0402; ProcessType: SMT; RoHS: Yes; Tolerance: 10%; Vendor: DigiKey; Vendor Part#: PCC103BQCT-ND; eI Part#: 03_00025_01
C59 C60 C114 = 11_C_0: CAP CER 0.1UF 10V 10% X5R 0402; Alt Mfg: Murata; Alt Mfg Part#: GRM155R61A104KA01D; Manufacture Part Number: 2238 787 15649||CC0402KRX7R7BB104; Mfg: Yageo; Mfg Part#: CC0402KRX5R6BB104; Oper. Temp. Range: -55C to 85C; Package: 0402; ProcessType: SMT; RoHS: Yes; Tolerance: 10%; Vendor: DigiKey; Vendor Part#: 311-1336-1-ND; Voltage: 10V; eI Part#: 03_00021_02
R37 R38 R41-R57 R59-R65 R86 = 10_R_0: RES 39.2 OHM 1/10W 1% 0402 SMD; Manufacture Part Number: 0402WGF392JTCE||RM04FTN39R2; Mfg: Panasonic - ECG; Mfg Part#: ERJ-2RKF39R2X; Oper. Temp. Range: -55C to 125C; Package: 0402; ProcessType: SMT; Remark: Alt part is 1/16W; RoHS: Yes; Tolerance: 1%; Vendor: DigiKey; Vendor Part#: P39.2LCT-ND; eI Part#: 02_00195_04
R58 = 10_R_0: RES 45.3 OHM 1/10W 1% 0402 SMD; Mfg: Panasonic - ECG; Mfg Part#: ERJ-2RKF45R3X; Oper. Temp. Range: -55C to 125C; Package: 0402; ProcessType: SMT; Remark: Alt part is 1/16W; RoHS: Yes; Tolerance: 1%; Vendor: DigiKey; Vendor Part#: P45.3LCT-ND; eI Part#: 02_00358_01
R66 = 10_R_0: RES 4.7K OHM 1/10W 5% 0402 SMD; Alt Mfg: Yageo; Alt Mfg Part#: RC0402JR-074K7L; Manufacture Part Number: 0402WGF392JTCE||RM04FTN39R2; Mfg: Panasonic - ECG; Mfg Part#: ERJ-2GEJ472X; Oper. Temp. Range: -55C to 125C; Package: 0402; ProcessType: SMT; Remark: Alt part is 1/16W; RoHS: Yes; Tolerance: 1%; Vendor: DigiKey; Vendor Part#: P4.7KJCT-ND; eI Part#: 02_00023_01
R69 R72 = 10_R_0: RES 2.00K OHM 1/10W 1% 0402 SMD; Alt Mfg: TE Connectivity; Alt Mfg Part#: 5-1879208-6; Manufacture Part Number: 0402WGF2001TCE||RM04FTN2001; Mfg: Panasonic - ECG; Mfg Part#: ERJ-2RKF2001X; Mounting Status: NU; Mounting_Status: NU; Oper. Temp. Range: -55C to 125C; Package: 0402; ProcessType: SMT; Remark: Alt part is 1/16W; RoHS: Yes; Tolerance: 1%; Vendor: DigiKey; Vendor Part#: P2.00KLCT-ND; eI Part#: 02_00229_02
R70 R71 = 10_R_0: RES 2.00K OHM 1/10W 1% 0402 SMD; Alt Mfg: TE Connectivity; Alt Mfg Part#: 5-1879208-6; Manufacture Part Number: 0402WGF2001TCE||RM04FTN2001; Mfg: Panasonic - ECG; Mfg Part#: ERJ-2RKF2001X; Oper. Temp. Range: -55C to 125C; Package: 0402; ProcessType: SMT; Remark: Alt part is 1/16W; RoHS: Yes; Tolerance: 1%; Vendor: DigiKey; Vendor Part#: P2.00KLCT-ND; eI Part#: 02_00229_02
R77 R78 = 10_R_0: RES 1.00K OHM 1/10W 1% 0402 SMD; Alt Mfg: Yageo; Alt Mfg Part#: RC0402FR-071KL; MOUNTED: <MOUNTED>; Manufacture Part Number: 0402WGF1001TCE||RM04FTN1001; Mfg: Panasonic - ECG; Mfg Part#: ERJ-2RKF1001X; Oper. Temp. Range: -55C to 125C; Package: 0402; ProcessType: SMT; RoHS: Yes; Tolerance: 1%; Vendor: DigiKey; Vendor Part#: P1.00KLCT-ND; eI Part#: 02_00045_01
B21 = 1212_FILTER_NFW31SP106X1E4L_0: FILTER LC HIGH FREQ 2200PF 0603; Manufacture Part Number: NFM18CC222R1C3D; Mfg: Murata; Mfg Part#: NFM18CC222R1C3D; Oper. Temp. Range: -55C to 125C; Package: 0603; ProcessType: SMT; RoHS: Yes; Tolerance: 20%; Vendor: DigiKey; Vendor Part#: NFM18CC222R1C3D-ND; eI Part#: 04_00026_01
C522 = 11_C_0: CAP CER 1.0UF 16V X5R 0402; Manufacture Part Number: C1005X5R0J105KT||C0402B105K007T; Mfg: TDK Corp; Mfg Part#: C1005X5R1C105K; Oper. Temp. Range: -55C to 85C; Package: 0402; ProcessType: SMT; RoHS: Yes; Tolerance: 10%; Vendor: DigiKey; Vendor Part#: 445-4978-1-ND; eI Part#: 03_00264_01
COM1 = CONNECTOR_-_3_X_1: CONN HEADER 3POS .100 VERT TIN; Mfg: Molex; Remarks: FP to be changed to MOL22-23-2031; RoHS: Yes; Specifications: CONN HEADER 3POS .100 VERT TIN; Vendor: DigiKey; Vendor Part#: WM4201-ND; eI Part#: 09_00155_01
COM_SEL1 = 1653_JH3X2V_0: PIN HEADER 3x2P 2.54mm 180D(M) DIP 201-2*3GS; Manufacture Part Number: 201-2*3GS 2.54mm||1130-010-06S||21N22564-06S10B-01G-6/3; Mfg: Samtec; ProcessType: DIP; RoHS: Yes; Vendor: Samtec; eI Part#: 09_00148_01
EEPROM1 = AT24C1024_0: IC EEPROM 1MBIT 1MHZ 8SOIC; Mfg: Atmel; Oper. Temp. Range: -40°C ~ 85°C; Package: 8-SOIC; RoHS: Yes; Vendor: DigiKey; Vendor Part#: AT24C1024BN-SH-T-ND; eI Part#: 01_00394_01
R95-R98 R104 R162 R163 R166 R180 R185-R188 R200 R204 R329 R330 R384 R955 R956 R964 R1106 R2107-R2110 R2204 R2960 R4000 = 10_R_0: RES 4.7K OHM 1/10W 5% 0402 SMD; Alt Mfg: Yageo; Alt Mfg Part#: RC0402JR-074K7L; Manufacture Part Number: 0402WGJ0472TCE||RC0402JR-074K7L||RM04JTN472; Mfg: Panasonic - ECG; Mfg Part#: ERJ-2GEJ472X; Oper. Temp. Range: -55C to 125C; Package: 0402; ProcessType: SMT; Remark: Alt part is 1/16W; RoHS: Yes; Tolerance: 5%; Vendor: DigiKey; Vendor Part#: P4.7KJCT-ND; eI Part#: 02_00023_01
R164 R343-R346 R349 R351 R352 R354-R359 R427-R429 R1601-R1604 = 10_R_0: RES ZERO OHM 1/10W 5% 0402 SMD; Alt Mfg: Yageo; Alt Mfg Part#: RC0402JR-070RL; Mfg: Panasonic - ECG; Mfg Part#: ERJ-2GE0R00X; Mounting Status: NU; Mounting_Status: NU; Oper. Temp. Range: -55C to 125C; Package: 0402; ProcessType: SMT; Remark: Alt part is 1/16W; RoHS: Yes; Tolerance: 5%; Vendor: DigiKey; Vendor Part#: P0.0JCT-ND; eI Part#: 02_00019_01
R137 R165 R167 R342 = 10_R_0: RES ZERO OHM 1/10W 5% 0402 SMD; Alt Mfg: Yageo; Alt Mfg Part#: RC0402JR-070RL; Mfg: Panasonic - ECG; Mfg Part#: ERJ-2GE0R00X; Oper. Temp. Range: -55C to 125C; Package: 0402; ProcessType: SMT; Remark: Alt part is 1/16W; RoHS: Yes; Tolerance: 5%; Vendor: DigiKey; Vendor Part#: P0.0JCT-ND; eI Part#: 02_00019_01
R202 R368 R369 = 10_R_0: RES 33.0 OHM 1/10W 1% 0402 SMD; Alt Mfg: Yageo; Alt Mfg Part#: RC0402FR-0733RL; Manufacture Part Number: 0402WGJ0330TCE||232270570339L||RC0402JR-0733RL||RM04JTN330; Mfg: Panasonic - ECG; Mfg Part#: ERJ-2RKF33R0X; Oper. Temp. Range: -55C to 125C; Package: 0402; ProcessType: SMT; Remark: Alt part is 1/16W; RoHS: Yes; Tolerance: 1%; Vendor: DigiKey; Vendor Part#: P33.0LCT-ND; eI Part#: 02_00018_05
R337 R340 R341 R347 R363 R398 R952 R953 = 10_R_0: RES 10.0 OHM 1/10W 1% 0402 SMD; Manufacture Part Number: 0402WGJ0100TCE||RC0402JR-0710RL||RM04JTN100; Mfg: Panasonic - ECG; Mfg Part#: ERJ-2RKF10R0X; Oper. Temp. Range: -55C to 125C; Package: 0402; ProcessType: SMT; RoHS: Yes; Tolerance: 1%; Vendor: DigiKey; Vendor Part#: P10.0LCT-ND; eI Part#: 02_00060_01
R455 R458-R472 = 10_R_0: RES 4.7K OHM 1/10W 5% 0402 SMD; Alt Mfg: Yageo; Alt Mfg Part#: RC0402JR-074K7L; MOUNTED: <MOUNTED>; Manufacture Part Number: 0402WGJ0472TCE||RC0402JR-074K7L||RM04JTN472; Mfg: Panasonic - ECG; Mfg Part#: ERJ-2GEJ472X; Oper. Temp. Range: -55C to 125C; Package: 0402; ProcessType: SMT; Remark: Alt part is 1/16W; RoHS: Yes; Tolerance: 5%; Vendor: DigiKey; Vendor Part#: P4.7KJCT-ND; eI Part#: 02_00023_01
R1227 = 10_R_0: RES 4.7K OHM 1/10W 5% 0402 SMD; Alt Mfg: Yageo; Alt Mfg Part#: RC0402JR-074K7L; Manufacture Part Number: 0402WGJ0472TCE||RC0402JR-074K7L||RM04JTN472; Mfg: Panasonic - ECG; Mfg Part#: ERJ-2GEJ472X; Mounting Status: NU; Mounting_Status: NU; Oper. Temp. Range: -55C to 125C; Package: 0402; ProcessType: SMT; Remark: Alt part is 1/16W; RoHS: Yes; Tolerance: 5%; Vendor: DigiKey; Vendor Part#: P4.7KJCT-ND; eI Part#: 02_00023_01
R1960-R1965 = 10_R_0: RES 4.7K OHM 1/10W 5% 0402 SMD; Alt Mfg: Yageo; Alt Mfg Part#: RC0402JR-074K7L; Mfg: Panasonic - ECG; Mfg Part#: ERJ-2GEJ472X; Oper. Temp. Range: -55C to 125C; Package: 0402; ProcessType: SMT; Remark: Alt part is 1/16W; RoHS: Yes; Tolerance: 5%; Vendor: DigiKey; Vendor Part#: P4.7KJCT-ND; eI Part#: 02_00023_01
TP10 TP11 TP134 TP135 = 00_TP-S40_0: TEST PAD TP-S40; Mfg: --NA--; Mfg Part#: --NA--; Oper. Temp. Range: --NA--; Package: --NA--; ProcessType: SMT; RoHS: Yes; Vendor: --NA--; Vendor Part#: --NA--; eI Part#: --NA--
U24 = SN74AVC4T245PWR: IC BUS TRANSCVR 4BIT 16TSSOP; Mfg: Texas Instruments; Oper. Temp. Range: -40°C ~ 85°C; Package: 16-TSSOP; RoHS: Yes; Specifications: IC BUS TRANSCVR 4BIT 16TSSOP; Vendor: Texas Instruments; eI Part#: 01_00045_01
U249 = MAX3221: IC RS232 3V-5.5V DRVR 16-TSSOP; Mfg: Texas Instruments; Package: 16-TSSOP; Vendor: Texas Instruments; eI Part#: 01_00390_01
U255 = 141_TI_SN74ALVC125PWR_0: IC BUS BUFF TRI-ST QD 14TSSOP; Mfg: Texas Instruments; Oper. Temp. Range: -40°C ~ 85°C; Package: TSSOP14; ProcessType: SMT; RoHS: Yes; Vendor: DigiKey; Vendor Part#: 296-5115-1-ND; eI Part#: 01_00845_01
U260 = 141_NUMONYX_N25Q128A21BSF40F: IC NOR Flash Mem Serial 1.8V 32M-Bit 4M x 8 7ns 8-Pin SO; Alt Mfg: Macronix; Alt Mfg Part#: MX25U3235EM2I-10G; Mfg: Micron; Package: SOP2-8; ProcessType: SMT; RoHS: Yes; Vendor: Arrow Electronics; eI Part#: 01_00851_01
B4-B6 = 1212_BEAD_0: FERRITE CHIP 120 OHM 500MA 0402; Manufacture Part Number: BLM15AG121SN1D; Mfg: Murata; Mfg Part#: BLM15AG121SN1D; Oper. Temp. Range: -55C to 85C; Package: 0402; ProcessType: SMT; RoHS: Yes; Tolerance: 25%; Vendor: DigiKey; Vendor Part#: 490-1005-1-ND; eI Part#: 04_00075_01
C130 C131 = 11_C_0: CAP CER 33PF 50V 5% NPO 0402; Manufacture Part Number: 223886915339; Mfg: Yageo; Mfg Part#: CC0402JRNPO9BN330; Oper. Temp. Range: -55C to 85C; Package: 0402; ProcessType: SMT; RoHS: Yes; Tolerance: 10%; Vendor: DigiKey; Vendor Part#: 311-1020-1-ND; eI Part#: 03_00019_01
C396 C601 = 11_C_0: CAP CER 10UF 6.3V 20% X5R 0603; Manufacture Part Number: C1608X5R0J106MT||2255 206 13776||CC0603MRX5R5BB106; Mfg: Murata; Mfg Part#: GRM188R60J106ME47D; Oper. Temp. Range: -55C to 85C; Package: 0603; ProcessType: SMT; RoHS: Yes; Tolerance: 20%; Vendor: DigiKey; Vendor Part#: 490-3896-1-ND; eI Part#: 03_00058_03
D4 D5 = 130_ESD_D0603_0: SUPPRESSOR ESD 24VDC 0603 SMD; Manufacture Part Number: PGB1010603NR; Mfg: Littelfuse Inc; Mfg Part#: PGB1010603MR; Package: 0603; ProcessType: SMT; RoHS: Yes; Vendor: DigiKey; Vendor Part#: F2594CT-ND; eI Part#: 05_00002_01
J4 J5 = CONNECTOR_-_2_X_1: CONN HEADER 2POS .100" THROUGH HOLE TIN; Mfg: Samtec; Oper. Temp. Range: -55C to 105C; RoHS: Yes; Specifications: CONN HEADER 2POS .100" THROUGH HOLE TIN; Vendor: Samtec; eI Part#: 09_00480_01
R88 R89 R91-R93 R100 R101 = 10_R_0: RES 22 OHM 1/10W 5% 0402 SMD; Mfg: Panasonic - ECG; Mfg Part#: ERJ-2GEJ220X; Oper. Temp. Range: -55C to 125C; Package: 0402; ProcessType: SMT; Remark: Alt part is 1/16W; RoHS: Yes; Tolerance: 5%; Vendor: DigiKey; Vendor Part#: P22JCT-ND; eI Part#: 02_00233_01
R94 = 10_R_0: RES 12.1K OHM 1/10W 1% 0603 SMD; Manufacture Part Number: 0603WAF1212T5E||232270461213L||RM06FTN1212; Mfg: Panasonic - ECG; Mfg Part#: ERJ-3EKF1212V; Oper. Temp. Range: -55C to 125C; Package: 0603; ProcessType: SMT; Remark: Alt part is 1/16W; RoHS: Yes; Tolerance: 1%; Vendor: DigiKey; Vendor Part#: P12.1KHCT-ND; eI Part#: 02_00499_02
R102 = 10_R_0: RES 2.2K OHM 1/10W 5% 0402 SMD; Alt Mfg: Yageo; Alt Mfg Part#: RC0402JR-072K2L; Manufacture Part Number: 0402WGJ0222TCE||RM04JTN222; Mfg: Panasonic - ECG; Mfg Part#: ERJ-2GEJ222X; Oper. Temp. Range: -55C to 125C; Package: 0402; ProcessType: SMT; Remark: Alt part is 1/16W; RoHS: Yes; Tolerance: 5%; Vendor: DigiKey; Vendor Part#: P2.2KJCT-ND; eI Part#: 02_00024_01
R103 R138 = 10_R_0: RES 10.0K OHM 1/10W 1% 0402 SMD; Alt Mfg: Yageo; Alt Mfg Part#: RC0402FR-0710KL; Manufacture Part Number: 0402WGF1002TCE||RM04FTN1002; Mfg: Panasonic - ECG; Mfg Part#: ERJ-2RKF1002X; Oper. Temp. Range: -55C ~ 125C; Package: 0402; ProcessType: SMT; Remark: Alt part is 1/16W; RoHS: Yes; Tolerance: 1%; Vendor: DigiKey; Vendor Part#: P10.0KLCT-ND; eI Part#: 02_00027_01
R171 = 10_R_0: RES 1.00K OHM 1/10W 1% 0402 SMD; Alt Mfg: Yageo; Alt Mfg Part#: RC0402FR-071KL; Manufacture Part Number: 0402WGF1001TCE||RM04FTN1001; Mfg: Panasonic - ECG; Mfg Part#: ERJ-2RKF1001X; Oper. Temp. Range: -55C to 125C; Package: 0402; ProcessType: SMT; RoHS: Yes; Tolerance: 1%; Vendor: DigiKey; Vendor Part#: P1.00KLCT-ND; eI Part#: 02_00045_01
R908 R909 R1910 = 10_R_0: RES 4.7K OHM 1/10W 5% 0402 SMD; Alt Mfg: Yageo; Alt Mfg Part#: RC0402JR-074K7L; Manufacture Part Number: RM04FTN4751; Mfg: Panasonic - ECG; Mfg Part#: ERJ-2GEJ472X; Oper. Temp. Range: -55C to 125C; Package: 0402; ProcessType: SMT; Remark: Alt part is 1/16W; RoHS: Yes; Tolerance: 5%; Vendor: DigiKey; Vendor Part#: P4.7KJCT-ND; eI Part#: 02_00023_01
U9 = FT2232H: IC USB UART/FIFO DUAL HS 64LQFP; Mfg: FTDI; Mfg Part#: FT2232HL - REEL; Oper. Temp. Range: -40C to 85C; Package: LQFP-64; RoHS: Yes; Specifications: IC USB UART/FIFO DUAL HS 64LQFP; Vendor: DigiKey; Vendor Part#: 768-1024-1-ND; eI Part#: 01_00392_01
U10 = TXS0108EPWR: IC 8BIT NON-INV TRANSLTR 20TSSOP; Mfg: Texas Instruments; Oper. Temp. Range: -55C to 85C; Package: 20-TSSOP; RoHS: Yes; Vendor: DigiKey; Vendor Part#: 296-23011-1-ND; eI Part#: 01_00472_01
U11 = SN74AHC00PWR: IC QUAD 2IN POS-NAND GTE 14TSSOP; Manufacture: ¼w¦{»ö¾¹¤u·~ªÑ¥÷¦³­­¤½¥q(Texas Instruments Incorporated); Manufacture Part Number: SN74LVC00APWR; Mfg: Texas Instruments; Package: TSSOP14; Part Number: 1410000164; ProcessType: SMT; RoHS: Yes; Vendor: DigiKey; Vendor Part#: 296-1080-1-ND; eI Part#: 01_00550_01
U12 = 141_ATMEL_AT93C46DN-SH-T_0: IC EEPROM 1KBIT 2MHZ 8SOIC; Mfg: Atmel; Oper. Temp. Range: -40°C ~ 85°C; Package: SOIC8; ProcessType: SMT; RoHS: Yes; Vendor: DigiKey; Vendor Part#: AT93C46DN-SH-T-ND; eI Part#: 01_00440_01
U254 U259 = TS3L301: IC LAN SWITCH 3V SPDT 48-TSSOP; Mfg: Texas Instruments; Vendor: Digikey; Vendor Part#: 296-17533-1-ND; eI Part#: 01_00397_01
U266 = SN74LVC1G08DCKR: SINGLE POSITIVE AND GATE SC-70; Mfg: Texas Instruments; Package: 6-TSSOP; RoHS: Yes; Vendor: DigiKey; Vendor Part#: 296-11602-1-ND; eI Part#: 01_00036_01
U267 = SN74LVC1G32DCKR: IC POSITIVE-OR GATE 2-IN SC-70; Mfg: Texas Instruments; Package: 6-TSSOP; RoHS: Yes; Vendor: DigiKey; Vendor Part#: 296-9848-1-ND; eI Part#: 01_00183_01
USB1 = Mini_USB_Connector: CONN USB RECEPTACLE 5POS RT ANG; Mfg: Molex; Package: MINIUSB5P, Through Hole; Part Number: 1654008501; RoHS: Yes; Vendor: Digikey; Vendor Part#: WM17115-ND; eI Part#: 09_00661_01
Y2 = CRYSTAL-4_PIN: CRYSTAL 12.000MHZ 18PF FUND SMD; Mfg: Abracon Corporation; Oper. Temp. Range: -20C to 60C; Package: 5.0mm x 3.2mm; RoHS: Yes; Specifications: CRYSTAL 12.000MHZ 18PF FUND SMD; Vendor: DigiKey; Vendor Part#: 535-9116-1-ND; eI Part#: 08_00068_01
DSP1 = TMS320C6657: TI DSP, Dual C66x™ DSP Cores; Mfg: Texas Instruments; RoHS: Yes; Vendor: Texas Instruments; eI Part#: 01_00878_01

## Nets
1V8_EMU_00: U10.7(A6) U254.31(5B2)
1V8_EMU_01: U10.8(A7) U254.26(6B2)
1V8_TCK: U10.1(A1) U254.45(0B2)
1V8_TDI: U10.3(A2) U254.44(1B2)
1V8_TDO: U10.4(A3) U254.39(2B2)
1V8_TMS: U10.5(A4) U254.38(3B2)
1V8_TRST#: U10.6(A5) U254.32(4B2)
3V3_EMU_00: U10.14(B6) U259.17(A5)
3V3_EMU_01: U10.13(B7) U259.21(A6)
3V3_TCK: U10.20(B1) U259.2(A0)
3V3_TDI: U10.18(B2) U259.4(A1)
3V3_TDO: U10.17(B3) U259.8(A2)
3V3_TMS: U10.16(B4) U259.10(A3)
3V3_TRST#: U10.15(B5) U259.15(A4)
GND: B6.2 B21.2(GND) C33.1 C34.2 C35.1 C36.2 C37.1 C38.2 C39.1 C40.2 C41.1 C42.2 C43.1 C44.2 C59.1 C114.2 C115.2 C116.2 C117.2 C118.2 C119.2 C120.2 C121.2 C122.2 C123.2 C124.1 C125.1 C126.2 C127.2 C129.2 C130.1 C131.1 C132.2 C133.2 C134.2 C135.1 C155.1 C157.2 C161.2 C303.1 C304.2 C365.2 C396.2 C472.1 C522.2 C601.2 C1367.2 C1368.1 C2226.2 C2227.2 COM1.1 EEPROM1.4(GND) J4.2 R58.2 R71.1 R72.1 R78.2 R94.1 R104.2 R138.1 R163.2 R164.1 R165.1 R166.1 R167.1 R171.1 R185.1 R186.1 R187.2 R188.2 R200.2 R204.1 R342.1 R343.2 R344.2 R345.2 R346.2 R349.2 R351.2 R352.2 R354.2 R355.2 R356.1 R357.1 R358.1 R359.1 R384.2 R455.1 R1106.1 R1227.2 R1601.1 R1602.1 R1603.1 R1604.1 R1962.1 R1963.1 R1964.1 R1965.1 U9.1(GND1) U9.5(GND1) U9.10(AGND) U9.11(GND1) U9.13(TEST) U9.15(GND1) U9.25(GND1) U9.35(GND1) U9.47(GND1) U9.51(GND1) U10.9(A8) U10.11(GND) U10.12(B8) U11.7(GND) U12.5(GND) U24.3(2DIR) U24.8(GND1) U24.9(GND2) U24.14(2~{OE}) U24.15(1~{OE}) U249.1(EN#) U249.14(GND) U254.3(GND[1]) U254.5(GND[2]) U254.7(GND[3]) U254.9(GND[4]) U254.11(GND[5]) U254.13(GND[6]) U254.16(GND[7]) U254.18(GND[8]) U254.20(GND[9]) U254.22(GND[10]) U254.27(GND[11]) U254.30(GND[12]) U254.33(GND[13]) U254.37(GND[14]) U254.40(GND[15]) U254.43(GND[16]) U254.46(GND[17]) U255.1(1~{OE}) U255.4(2~{OE}) U255.7(GND) U255.10(3~{OE}) U255.12(4A) U259.3(GND[1]) U259.5(GND[2]) U259.7(GND[3]) U259.9(GND[4]) U259.11(GND[5]) U259.13(GND[6]) U259.16(GND[7]) U259.18(GND[8]) U259.20(GND[9]) U259.22(GND[10]) U259.27(GND[11]) U259.30(GND[12]) U259.33(GND[13]) U259.37(GND[14]) U259.40(GND[15]) U259.43(GND[16]) U259.46(GND[17]) U260.4(VSS) U266.3(GND) U267.3(GND) USB1.4(GND_1) USB1.5(GND_2) Y2.2 Y2.4 ; also on sheet 7 8 9 12 13 14 15 16 19 20 23 26 27 28 29
GND_USB: B6.1 D4.1 D5.1 USB1.6(PTH1) USB1.7(PTH2)
VCC0V75: C33.2 C34.1 C35.2 C36.1 C37.2 C38.1 C39.2 C40.1 C41.2 C42.1 C43.2 C44.1 R41.2 R42.2 R43.2 R44.2 R45.2 R46.2 R47.2 R48.2 R49.2 R50.2 R51.2 R52.2 R53.2 R54.2 R55.2 R56.2 R57.2 R59.2 R60.2 R61.2 R62.2 R63.2 R64.2 R65.2 R86.2 ; also on sheet 15
VCC1V5: C31.1 C60.2 R66.2 R77.1 ; also on sheet 7 8 9 14 15
VCC1V8: B21.3(OUT) C303.2 C304.1 C1368.2 EEPROM1.8(VCC) R69.2 R70.2 R162.2 R180.2 R427.2 R428.2 R429.2 R458.1 R459.1 R460.1 R461.1 R462.1 R463.1 R464.1 R465.1 R466.1 R467.1 R468.1 R469.1 R470.1 R471.1 R472.1 R955.1 R964.2 R1960.2 R1961.2 R2204.1 R2960.2 R4000.1 U24.16(VCCB) U260.8(VCC) ; also on sheet 9 12 13 15 16 28
VCC1V8_AUX: C117.1 C118.1 C119.1 C125.2 U9.12(VCORE1) U9.37(VCORE2) U9.64(VCORE3) U10.2(VCCA) ; also on sheet 12 15 26 29
VCC3V3_AUX: B4.1 B5.1 C120.1 C121.1 C122.1 C123.1 C124.2 C132.1 C133.1 C134.1 C135.2 C161.1 C365.1 C396.1 C472.2 C522.1 C601.1 C1367.1 C2226.1 C2227.1 J5.1 R96.2 R97.2 R98.2 R103.2 R329.1 R330.1 R908.2 R909.2 R956.2 R1910.1 R2107.2 R2108.2 R2109.2 R2110.2 U9.20(VCCIO1) U9.31(VCCIO2) U9.42(VCCIO3) U9.56(VCCIO4) U10.19(VCCB) U11.14(VCC) U12.8(VCC) U24.1(VCCA) U24.2(1DIR) U249.15(VCC) U254.1(VDD[1]) U254.6(VDD[2]) U254.12(VDD[3]) U254.19(VDD[4]) U254.36(VDD[5]) U259.1(VDD[1]) U259.6(VDD[2]) U259.12(VDD[3]) U259.19(VDD[4]) U259.36(VDD[5]) U266.5(VCC) U267.5(VCC) ; also on sheet 12 13 14 15 16 20 23 26 27 28 29
VCC5_VBUS: R95.1 R137.1
AMC_JTAG_RST#: U259.35(4B1) ; also on sheet 12
AMC_JTAG_TCK: U259.48(0B1) ; also on sheet 12
AMC_JTAG_TDI: U259.47(1B1) ; also on sheet 12
AMC_JTAG_TDO: U259.42(2B1) ; also on sheet 12
AMC_JTAG_TMS: U259.41(3B1) ; also on sheet 12
DSP0_DDR3_EA0: DSP1.D16(DDRA00) R41.1 ; also on sheet 8
DSP0_DDR3_EA1: DSP1.A19(DDRA01) R42.1 ; also on sheet 8
DSP0_DDR3_EA2: DSP1.E16(DDRA02) R43.1 ; also on sheet 8
DSP0_DDR3_EA3: DSP1.E15(DDRA03) R44.1 ; also on sheet 8
DSP0_DDR3_EA4: DSP1.B18(DDRA04) R45.1 ; also on sheet 8
DSP0_DDR3_EA5: DSP1.A17(DDRA05) R46.1 ; also on sheet 8
DSP0_DDR3_EA6: DSP1.C16(DDRA06) R47.1 ; also on sheet 8
DSP0_DDR3_EA7: DSP1.A18(DDRA07) R48.1 ; also on sheet 8
DSP0_DDR3_EA8: DSP1.D20(DDRA08) R49.1 ; also on sheet 8
DSP0_DDR3_EA9: DSP1.E20(DDRA09) R50.1 ; also on sheet 8
DSP0_DDR3_EA10: DSP1.E19(DDRA10) R51.1 ; also on sheet 8
DSP0_DDR3_EA11: DSP1.B20(DDRA11) R52.1 ; also on sheet 8
DSP0_DDR3_EA12: DSP1.D18(DDRA12) R53.1 ; also on sheet 8
DSP0_DDR3_EA13: DSP1.C20(DDRA13) R54.1 ; also on sheet 8
DSP0_DDR3_EA14: DSP1.E18(DDRA14) R55.1 ; also on sheet 8
DSP0_DDR3_EA15: DSP1.E17(DDRA15) R86.1 ; also on sheet 8
DSP0_DDR3_EBA_0: DSP1.C18(DDRBA0) R56.1 ; also on sheet 8
DSP0_DDR3_EBA_1: DSP1.D17(DDRBA1) R57.1 ; also on sheet 8
DSP0_DDR3_EBA_2: DSP1.B19(DDRBA2) R59.1 ; also on sheet 8
DSP0_DDR3_ECAS#: DSP1.D14(DDRCASz) R63.1 ; also on sheet 8
DSP0_DDR3_ECC0: DSP1.D11(DDRCB00) ; also on sheet 8
DSP0_DDR3_ECC1: DSP1.B12(DDRCB01) ; also on sheet 8
DSP0_DDR3_ECC2: DSP1.C11(DDRCB02) ; also on sheet 8
DSP0_DDR3_ECC3: DSP1.A12(DDRCB03) ; also on sheet 8
DSP0_DDR3_ECKE_0: DSP1.A16(DDRCKE0) R64.1 ; also on sheet 8
DSP0_DDR3_ECKN_0: DSP1.B14(DDRCLKOUTN0) R38.1 ; also on sheet 8
DSP0_DDR3_ECKP_0: DSP1.A14(DDRCLKOUTP0) R37.1 ; also on sheet 8
DSP0_DDR3_ECS_0#: DSP1.B15(DDRCE0z) R65.1 ; also on sheet 8
DSP0_DDR3_EDM_0: DSP1.A8(DDRDQM0) ; also on sheet 8
DSP0_DDR3_EDM_1: DSP1.E7(DDRDQM1) ; also on sheet 8
DSP0_DDR3_EDM_2: DSP1.F5(DDRDQM2) ; also on sheet 8
DSP0_DDR3_EDM_3: DSP1.E1(DDRDQM3) ; also on sheet 8
DSP0_DDR3_EDM_4: DSP1.C12(DDRDQM8) ; also on sheet 8
DSP0_DDR3_EDQ0: DSP1.A9(DDRD00) ; also on sheet 8
DSP0_DDR3_EDQ1: DSP1.C9(DDRD01) ; also on sheet 8
DSP0_DDR3_EDQ2: DSP1.D9(DDRD02) ; also on sheet 8
DSP0_DDR3_EDQ3: DSP1.B9(DDRD03) ; also on sheet 8
DSP0_DDR3_EDQ4: DSP1.E9(DDRD04) ; also on sheet 8
DSP0_DDR3_EDQ5: DSP1.E10(DDRD05) ; also on sheet 8
DSP0_DDR3_EDQ6: DSP1.A11(DDRD06) ; also on sheet 8
DSP0_DDR3_EDQ7: DSP1.B11(DDRD07) ; also on sheet 8
DSP0_DDR3_EDQ8: DSP1.E6(DDRD08) ; also on sheet 8
DSP0_DDR3_EDQ9: DSP1.E8(DDRD09) ; also on sheet 8
DSP0_DDR3_EDQ10: DSP1.A6(DDRD10) ; also on sheet 8
DSP0_DDR3_EDQ11: DSP1.A5(DDRD11) ; also on sheet 8
DSP0_DDR3_EDQ12: DSP1.D6(DDRD12) ; also on sheet 8
DSP0_DDR3_EDQ13: DSP1.C7(DDRD13) ; also on sheet 8
DSP0_DDR3_EDQ14: DSP1.D7(DDRD14) ; also on sheet 8
DSP0_DDR3_EDQ15: DSP1.B8(DDRD15) ; also on sheet 8
DSP0_DDR3_EDQ16: DSP1.E5(DDRD16) ; also on sheet 8
DSP0_DDR3_EDQ17: DSP1.B3(DDRD17) ; also on sheet 8
DSP0_DDR3_EDQ18: DSP1.F4(DDRD18) ; also on sheet 8
DSP0_DDR3_EDQ19: DSP1.E4(DDRD19) ; also on sheet 8
DSP0_DDR3_EDQ20: DSP1.A3(DDRD20) ; also on sheet 8
DSP0_DDR3_EDQ21: DSP1.B5(DDRD21) ; also on sheet 8
DSP0_DDR3_EDQ22: DSP1.C5(DDRD22) ; also on sheet 8
DSP0_DDR3_EDQ23: DSP1.D5(DDRD23) ; also on sheet 8
DSP0_DDR3_EDQ24: DSP1.E2(DDRD24) ; also on sheet 8
DSP0_DDR3_EDQ25: DSP1.F2(DDRD25) ; also on sheet 8
DSP0_DDR3_EDQ26: DSP1.B1(DDRD26) ; also on sheet 8
DSP0_DDR3_EDQ27: DSP1.C1(DDRD27) ; also on sheet 8
DSP0_DDR3_EDQ28: DSP1.D1(DDRD28) ; also on sheet 8
DSP0_DDR3_EDQ29: DSP1.D3(DDRD29) ; also on sheet 8
DSP0_DDR3_EDQ30: DSP1.C3(DDRD30) ; also on sheet 8
DSP0_DDR3_EDQ31: DSP1.E3(DDRD31) ; also on sheet 8
DSP0_DDR3_EDQSN_0: DSP1.C10(DDRDQS0N) ; also on sheet 8
DSP0_DDR3_EDQSN_1: DSP1.A7(DDRDQS1N) ; also on sheet 8
DSP0_DDR3_EDQSN_2: DSP1.A4(DDRDQS2N) ; also on sheet 8
DSP0_DDR3_EDQSN_3: DSP1.B2(DDRDQS3N) ; also on sheet 8
DSP0_DDR3_EDQSN_4: DSP1.A13(DDRDQS8N) ; also on sheet 8
DSP0_DDR3_EDQSP_0: DSP1.D10(DDRDQS0P) ; also on sheet 8
DSP0_DDR3_EDQSP_1: DSP1.B7(DDRDQS1P) ; also on sheet 8
DSP0_DDR3_EDQSP_2: DSP1.B4(DDRDQS2P) ; also on sheet 8
DSP0_DDR3_EDQSP_3: DSP1.A2(DDRDQS3P) ; also on sheet 8
DSP0_DDR3_EDQSP_4: DSP1.B13(DDRDQS8P) ; also on sheet 8
DSP0_DDR3_EMRESETN: DSP1.B16(DDRRESETz) R66.1 ; also on sheet 8
DSP0_DDR3_EODT_0: DSP1.E14(DDRODT0) R60.1 ; also on sheet 8
DSP0_DDR3_ERAS#: DSP1.A15(DDRRASz) R62.1 ; also on sheet 8
DSP0_DDR3_EWE#: DSP1.E13(DDRWEz) R61.1 ; also on sheet 8
DSP_BOOTCOMPLETE: DSP1.H3(BOOTCOMPLETE) ; also on sheet 29
DSP_CORESEL0: DSP1.J5(CORESEL0) ; also on sheet 29
DSP_CORESEL1: DSP1.G5(CORESEL1) ; also on sheet 29
DSP_EMU_00: U254.17(A5) ; also on sheet 16
DSP_EMU_01: U254.21(A6) ; also on sheet 16
DSP_GPIO_00: DSP1.T25(GPIO00/LENDIAN) R455.2 ; also on sheet 26
DSP_GPIO_01: DSP1.R25(GPIO01/BOOTMODE00) R458.2 ; also on sheet 26
DSP_GPIO_02: DSP1.R23(GPIO02/BOOTMODE01) R459.2 ; also on sheet 26
DSP_GPIO_03: DSP1.U25(GPIO03/BOOTMODE02) R460.2 ; also on sheet 26
DSP_GPIO_04: DSP1.T23(GPIO04/BOOTMODE03) R461.2 ; also on sheet 26
DSP_GPIO_05: DSP1.U24(GPIO05/BOOTMODE04) R462.2 ; also on sheet 26
DSP_GPIO_06: DSP1.T22(GPIO06/BOOTMODE05) R463.2 ; also on sheet 26
DSP_GPIO_07: DSP1.R21(GPIO07/BOOTMODE06) R464.2 ; also on sheet 26
DSP_GPIO_08: DSP1.U22(GPIO08/BOOTMODE07) R465.2 ; also on sheet 26
DSP_GPIO_09: DSP1.U23(GPIO09/BOOTMODE08) R466.2 ; also on sheet 26
DSP_GPIO_10: DSP1.V23(GPIO10/BOOTMODE09) R467.2 ; also on sheet 26
DSP_GPIO_11: DSP1.U21(GPIO11/BOOTMODE10) R468.2 ; also on sheet 26
DSP_GPIO_12: DSP1.T21(GPIO12/BOOTMODE11) R469.2 ; also on sheet 26
DSP_GPIO_13: DSP1.V22(GPIO13/BOOTMODE12) R470.2 ; also on sheet 26
DSP_GPIO_14: R952.1 ; also on sheet 23 26
DSP_GPIO_15: R953.1 ; also on sheet 23 26
DSP_GPIO_R_14: DSP1.W21(GPIO14/PCIESSMODE0) R471.2 R952.2
DSP_GPIO_R_15: DSP1.V21(GPIO15/PCIESSMODE1) R472.2 R953.2
DSP_HOUT: DSP1.G2(HOUT) ; also on sheet 29
DSP_LRESETNMIENZ: DSP1.F1(LRESETNMIENz) R2204.2 ; also on sheet 29
DSP_LRESETZ: DSP1.G4(LRESETz) ; also on sheet 29
DSP_NMIZ: DSP1.H1(NMIz) ; also on sheet 29
DSP_PORZ: DSP1.Y18(PORz) R187.1 ; also on sheet 29
DSP_RESETFULLZ: DSP1.J4(RESETFULLz) R188.1 ; also on sheet 29
DSP_RESETSTAT#: DSP1.H5(RESETSTATz) ; also on sheet 29
DSP_RESETZ: DSP1.H4(RESETz) R200.1 ; also on sheet 29
DSP_SCL: DSP1.AA17(SCL) EEPROM1.6(SCL) R180.1 ; also on sheet 12 23
DSP_SDA: DSP1.AA18(SDA) EEPROM1.5(SDA) R964.1 ; also on sheet 12 23
DSP_SSPCK: R340.2 U255.2(1A) U255.5(2A) U255.9(3A)
DSP_SSPCS0: R337.2 R1960.1 U260.1(~{S})
DSP_SSPCS1: DSP1.AA14(GPIO29/SPISCS1) R1961.1 ; also on sheet 23 29
DSP_SSPMISO: DSP1.AB14(GPIO30/SPIDIN) R166.2 R398.1 ; also on sheet 23 29
DSP_SSPMOSI: R363.2 U260.5(DQ0) ; also on sheet 23 29
DSP_TCK: U254.2(A0) ; also on sheet 16
DSP_TDI: U254.4(A1) ; also on sheet 16
DSP_TDO: U254.8(A2) ; also on sheet 16
DSP_TIMI0: DSP1.AD20(TIMI0/GPIO16) R186.2 ; also on sheet 23 26
DSP_TIMI1: DSP1.AE21(TIMI1/GPIO17) R185.2 ; also on sheet 23 26
DSP_TIMO0: R341.1 ; also on sheet 23 26
DSP_TIMO1: R347.1 ; also on sheet 23 26
DSP_TMS: U254.10(A3) ; also on sheet 16
DSP_TRST#: U254.15(A4) ; also on sheet 16
DSP_UART0_CTS: TP134.1 U24.4(1A1)
DSP_UART0_RTS: TP135.1 U24.6(2A1)
DSP_UART0_RX: COM_SEL1.4 U24.5(1A2)
DSP_UART0_TX: COM_SEL1.3 U24.7(2A2)
DSP_UART1_CTS: DSP1.AE16(GPIO26/UARTCTS1) R1965.2 ; also on sheet 23
DSP_UART1_RTS: DSP1.AD15(GPIO27/UARTRTS1) ; also on sheet 23
DSP_UART1_RX: DSP1.AC14(GPIO24/UARTRXD1) R1964.2 ; also on sheet 23
DSP_UART1_TX: DSP1.AC15(GPIO25/UARTTXD1) ; also on sheet 23
DSP_UARTCTS_V1P8: DSP1.AC17(GPIO22/UARTCTS) R1963.2 U24.13(1B1)
DSP_UARTRTS_V1P8: DSP1.AB17(GPIO23/UARTRTS) U24.11(2B1)
DSP_UARTRXD_V1P8: DSP1.AB15(GPIO20/UARTRXD) R1962.2 U24.12(1B2)
DSP_UARTTXD_V1P8: DSP1.AA15(GPIO21/UARTTXD) U24.10(2B2)
DSP_VREFSSTL: C59.2 C60.1 C114.1 DSP1.E12(VREFSSTL) R77.2 R78.1 ; also on sheet 8 15
EEPROM_WP: EEPROM1.7(WP) R1227.1 R4000.2 ; also on sheet 29
EMU_EMU_00: U254.34(5B1) ; also on sheet 16
EMU_EMU_01: U254.29(6B1) ; also on sheet 16
EMU_TCK_BUF: U254.48(0B1) ; also on sheet 16
EMU_TDI: U254.47(1B1) ; also on sheet 16
EMU_TDO: U254.42(2B1) ; also on sheet 16
EMU_TMS: U254.41(3B1) ; also on sheet 16
EMU_TRST#: U254.35(4B1) ; also on sheet 16
EXT_EMU_DET0: U267.1(A) ; also on sheet 16
FPGA_SSPCK: R202.2 ; also on sheet 29
FT2232HL_RESET#: R95.2 R138.2 U9.14(~{RESET}) U266.2(B)
FT_EMU0: R100.1 U259.31(5B2)
FT_EMU1: R101.1 U259.26(6B2)
FT_TDI: R89.1 R2108.1 U259.44(1B2)
FT_TDK: R88.1 R2107.1 U259.45(0B2)
FT_TDO: R91.1 R2109.1 U259.39(2B2)
FT_TMS: R92.1 R2110.1 U259.38(3B2)
FT_TRST#: R93.1 R171.2 U259.32(4B2)
GPIOL1: R96.1 U9.22(GPIOL1) U11.13(B)
GPIOL2: U9.23(GPIOL2) U11.5(B)
GPIOL3: U9.24(GPIOL3) U11.10(B)
NOR_HD#: R162.1 U260.7(~{HOL}D/DQ3)
NOR_SSPCK: R369.1 U260.6(SCK)
NOR_WP#: R163.1 U260.3(~{W}/Vpp/DQ2) ; also on sheet 29
PH_SSPCK: R368.1 ; also on sheet 23
RS232_RX: COM1.3 U249.8(RIN)
RS232_TX: COM1.2 U249.13(DOUT)
U1_DDRSLRATE0: DSP1.C22(DDRSLRATE0) R69.1 R71.2
U1_DDRSLRATE1: DSP1.D22(DDRSLRATE1) R70.1 R72.2
UART_FT_RX: COM_SEL1.2 U9.38(BDBUS0/TXD) ; also on sheet 23
UART_FT_TX: COM_SEL1.1 R204.2 U9.39(BDBUS1/RXD) ; also on sheet 23
UART_MAX_RX: COM_SEL1.6 U249.9(ROUT)
UART_MAX_TX: COM_SEL1.5 R384.1 U249.11(DIN)
USB_DM: D4.2 U9.7(DM) USB1.2(D-)
USB_DP: D5.2 U9.8(DP) USB1.3(D+)
VPHY: B5.2 C126.1 C127.1 U9.4(VPHY)
VPLL: B4.2 C115.1 C116.1 U9.9(VPLL)
N34886870: EEPROM1.2(A1) R165.2 R428.1
N34886871: EEPROM1.1(NC) R164.2 R427.1
N34886872: EEPROM1.3(A2) R167.2 R429.1
N35057140: DSP1.F15(PTV15) R58.1
N35276268: C31.2 R37.2 R38.2
N44669566: DSP1.AC19(TIMO0/GPIO18) R341.2
N49340071: DSP1.AA12(GPIO28/SPISCS0) R337.1
N49343775: DSP1.AA13(SPICLK) R340.1
N49345539: DSP1.AB13(GPIO31/SPIDOUT) R363.1
N56717107: R398.2 U260.2(DQ1)
N58478603: DSP1.AE20(TIMO1/GPIO19) R347.2
N60593300: R368.2 U255.6(2Y)
N61905227: R202.1 U255.8(3Y)
N61928373: B21.1(IN) U255.13(4~{OE}) U255.14(VCC)
N61931994: R369.2 U255.3(1Y)
N67264129: DSP1.H2(RSV03) R1602.2
N67265956: DSP1.Y19(RSV08) R1603.2
N67267779: DSP1.C23(RSV09) R1604.2
N67314000: DSP1.AC18(RSV04) R358.2
N67314013: DSP1.AB18(RSV05) R359.2
N67327503: DSP1.B23(RSV06) R356.2
N67327507: DSP1.A23(RSV07) R357.2
N67333345: DSP1.G21(RSV15) R346.1
N67333358: DSP1.F21(RSV14) R349.1
N67333371: DSP1.J20(RSV16) R351.1
N67333375: DSP1.AA7(RSV17) R352.1
N67335579: DSP1.G22(RSV10) R342.2
N67335594: DSP1.H22(RSV11) R343.1
N67347851: DSP1.Y5(RSV12) R344.1
N67350373: DSP1.Y4(RSV13) R345.1
N67362685: DSP1.AA11(RSV18) R354.1
N67362689: DSP1.AB3(RSV19) R355.1
N67364880: DSP1.AA22(RSV01) R2960.1
N67368866: DSP1.J3(RSV02) R1601.2
N70107445: C156.2 U249.6(C2-)
N70107453: C154.2 U249.2(C1+)
N70107455: R329.2 U249.16(FORCEOFF#)
N70107459: C154.1 U249.4(C1-)
N70107518: C155.2 U249.3(V+)
N70107528: C157.1 U249.7(V-)
N70107534: R330.2 U249.12(FORCEON)
N70107538: C156.1 U249.5(C2+)
N70983040: C129.1 R137.2 USB1.1(VBUS)
N71065759: C130.2 U9.2(OSCI) Y2.1
N71065761: C131.2 U9.3(OSCO) Y2.3
N71079292: R94.2 U9.6(REF)
N71094463: R956.1 U12.6(ORG)
N71094529: R102.2 U9.61(EEDATA) U12.3(DI)
N71094537: R102.1 R103.1 U12.4(DO)
N71094551: U9.63(EECS) U12.1(CS)
N71108285: U9.62(EECLK) U12.2(SK)
N71174595: TP10.1 U9.60(~{PWREN})
N71174866: TP11.1 U9.36(~{SUSPEND})
N71180994: R97.1 U11.12(A)
N71181167: R98.1 U11.4(A) U11.9(A) U11.11(Y)
N71255386: R101.2 U11.8(Y)
N71270545: R104.1 U11.1(A) U11.2(B)
N71296375: R88.2 U9.16(TCK)
N71296378: R89.2 U9.17(TDI)
N71296381: R91.2 U9.18(TDO)
N71296384: R92.2 U9.19(TMS)
N71296387: R93.2 U9.21(GPIOL0)
N71497416: R955.2 U10.10(OE)
N71497476: R100.2 U11.6(Y)
N74420054: R908.1 U259.34(5B1)
N74420056: R909.1 U259.29(6B1)
N77532754: J4.1 R1910.2 U266.1(A)
N78298892: U259.24(SEL) U266.4(Y)
N79151070: U254.24(SEL) U267.4(Y)
N79151074: J5.2 R1106.2 U267.2(B)

Not connected (* = marked no-connect by the designer): DSP1 A20(DDRCKE1)* A21(DDRCLKOUTP1)* B21(DDRCLKOUTN1)* C14(DDRCE1z)* D12(DDRODT1)*; U9 26(GPIOH0)* 27(GPIOH1)* 28(GPIOH2)* 29(GPIOH3)* 30(GPIOH4)* 32(GPIOH5)* 33(GPIOH6)* 34(GPIOH7)* 40(BDBUS2)* 41(BDBUS3)* 43(BDBUS4)* 44(BDBUS5)* 45(BDBUS6)* 46(BDBUS7)* 48(BCBUS0)* 49(VREGOUT)* 50(VREGIN)* 52(BCBUS1)* 53(BCBUS2)* 54(BCBUS3)* 55(BCBUS4)* 57(BCBUS5)* 58(BCBUS6)* 59(BCBUS7)*; U11 3(Y)*; U12 7(NC)*; U249 10(INVALID#)*; U254 14(NC)* 23(A7)* 25(7B2)* 28(7B1)*; U255 11(4Y)*; U259 14(NC)* 23(A7)* 25(7B2)* 28(7B1)*

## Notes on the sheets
sheet 1
- POWER SEQUENCE
sheet 2
- TMDSEVM6657 SCHEMATIC
- MAJOR REVISION HISTORY :
- I2C ADDRESS TABLE :
- PCB REV.
- SCH. REV.
- DESCRIPTION
- DATE
- REF DES
- DESCRIPTION
- 7 BIT ADDRESS
- 1.0
- 0.6
- Initial Draft
- 03-FEB-2012
- EEPROM1
- DSP EEPROM
- 0x50, 0x51
- 1.1
- Release for Alpha Boards
- 20-MAR-2012
- U264
- ETHERNET EEPROM
- 0x50
- 2.0
- 2.5
- Release for Beta Boards
- 26-JUL-2012
- 2.9
- Redundant pull-up and termination NU
  on EMU_TCK
- 28-NOV-2013
- PCB LAYER STACK-UP DETAILS :
- PCB MECHANICAL DETAILS :
- TOP
- 1.0 oz
- 1. PCB SIZE: 7.11" x 2.89" x 0.063"
  2. PCB MATERIAL: FR4_IT168G
  3. NUMBER OF LAYERS: 12
  4. IMPEDANCE CONTROL: YES
- 3.6mils
- p.p
- L2_GND
- 1.0 oz
- 4mils
- core
- L3
- 0.5 oz
- 4.8mils
- p.p
- L4_PWR
- 1.0 oz
- 5mils
- core
- L5
- 0.5 oz
- 4.4mils
- p.p
- L6_GND
- 1.0 oz
- 4mils
- core
- NOTES, UNLESS OTHERWISE SPECIFIED :
- 1.0 oz
- L7_GND
- 4.4mils
- p.p
- L8
- 0.5 oz
- 5mils
- core
- 1.0 oz
- L9_PWR
- 1. RESISTANCE VALUES ARE IN OHMS.
  2. CAPACITANCE VALUES ARE IN MICROFARADS.
  3. PARTS NOT INSTALLED ARE INDICATED WITH 'NU'.
  4. SIGNAL NET NAMES WITH "#" SUFFIX, ARE ACTIVE LOW SIGNALS.
- 4.8mils
- p.p
- L10
- 0.5 oz
- 4mils
- core
- 1.0 oz
- L11_GND
- 3.6mils
- p.p
- BOT
- 1.0 oz
- DISCLAIMER: THIS CIRCUIT DESIGN IS
  PROVIDED AS REFERENCE ONLY,
  WITHOUT WARRANTY EXPRESSED OR
  IMPLIED. THE USER IS ENCOURAGED
  TO PERFORM ALL DUE DILIGENCE WITH
  RESPECT TO DESIGN AND ANALYSIS.
  FOR COMMITTED PERFORMANCE AND
  FUNCTIONALITY OF THE xxxx DEVICE,
  PLEASE REFER TO THE DEVICE DATA
  MANUAL.
- Copyright (C) 20xx Texas Instruments Incorporated.
  All rights reserved.
sheet 3
- PLACEMENT
sheet 4
- I2C, TIMER[1:0], SPI
- 1Mb I2C EEPROM
- 32Mb SPI NOR Flash
- Read Address: 1010 0001 (0x50), 1010 0011 (0x51)
  Write Address: 1010 0000 (0x50), 010 0010 (0x51)
- GPIO
- UART to RS232
- JP-UART(1-3) & (2-4) : UART over USB Connector (Default)
  JP-UART(3-5) & (4-6) : UART over 3-Pin Header J5
- Reset Control
- DIR = 0 --> B to A
  DIR = 1 --> A to B
- Reserved
sheet 5
- DDR3 INTERFACE
- Place these resistors at the end of the trace.
- 20 mil trace width
- DDR3 Slew-Rate Setting (DDRSLRATE[1:0]):
  00    Fastest
  01    Fast
  10    Slow
  11    Slowest
sheet 6
- USB, JTAG
- 90 OHM DIFF. IMPEDANCE CONTROL
- Switch for JTAG emulation
  FT2232HL_RESET# = 0 --> AMC
  FT2232HL_RESET# = 1 --> Mini USB
- OR GATE
- Switch for JTAG emulation
  EXT_EMU_DET = 0 --> External / Mezzanine Emulator
  EXT_EMU_DET = 1 --> On board emulation
